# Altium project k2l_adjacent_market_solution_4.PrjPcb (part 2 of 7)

## Sheet k2l_soc_03_1.SchDoc
size 431 x 279 mm; Date: Not shown in title block; ApprovedBy: Not shown in title block; CheckedBy: Not shown in title block; Author: Not shown in title block; CompanyName: Not shown in title block; Engineer: Not shown in title block; Organization: Not shown in title block; Address1: Not shown in title block; Address2: Not shown in title block; Address3: Not shown in title block; Address4: Not shown in title block; DocumentNumber: 8; Revision: Use project parameter SCH_Rev; SheetNumber: 8; SheetTotal: 38; PageSetup: Record=PageOptions¦CenterHorizontal=True¦CenterVertical=True¦PrintScale=1.00¦XCorrection=1.00¦YCorrection=1.00¦PrintKind=0¦BorderSize=5000000¦LeftOffset=0¦BottomOffset=0¦Orientation=2¦PaperLength=1000¦PaperWidth=1000¦Scale=100¦PaperSource=15¦PrintQuality=600¦MediaType=1¦DitherType=10¦PaperKind=Letter¦PrintScaleMode=1
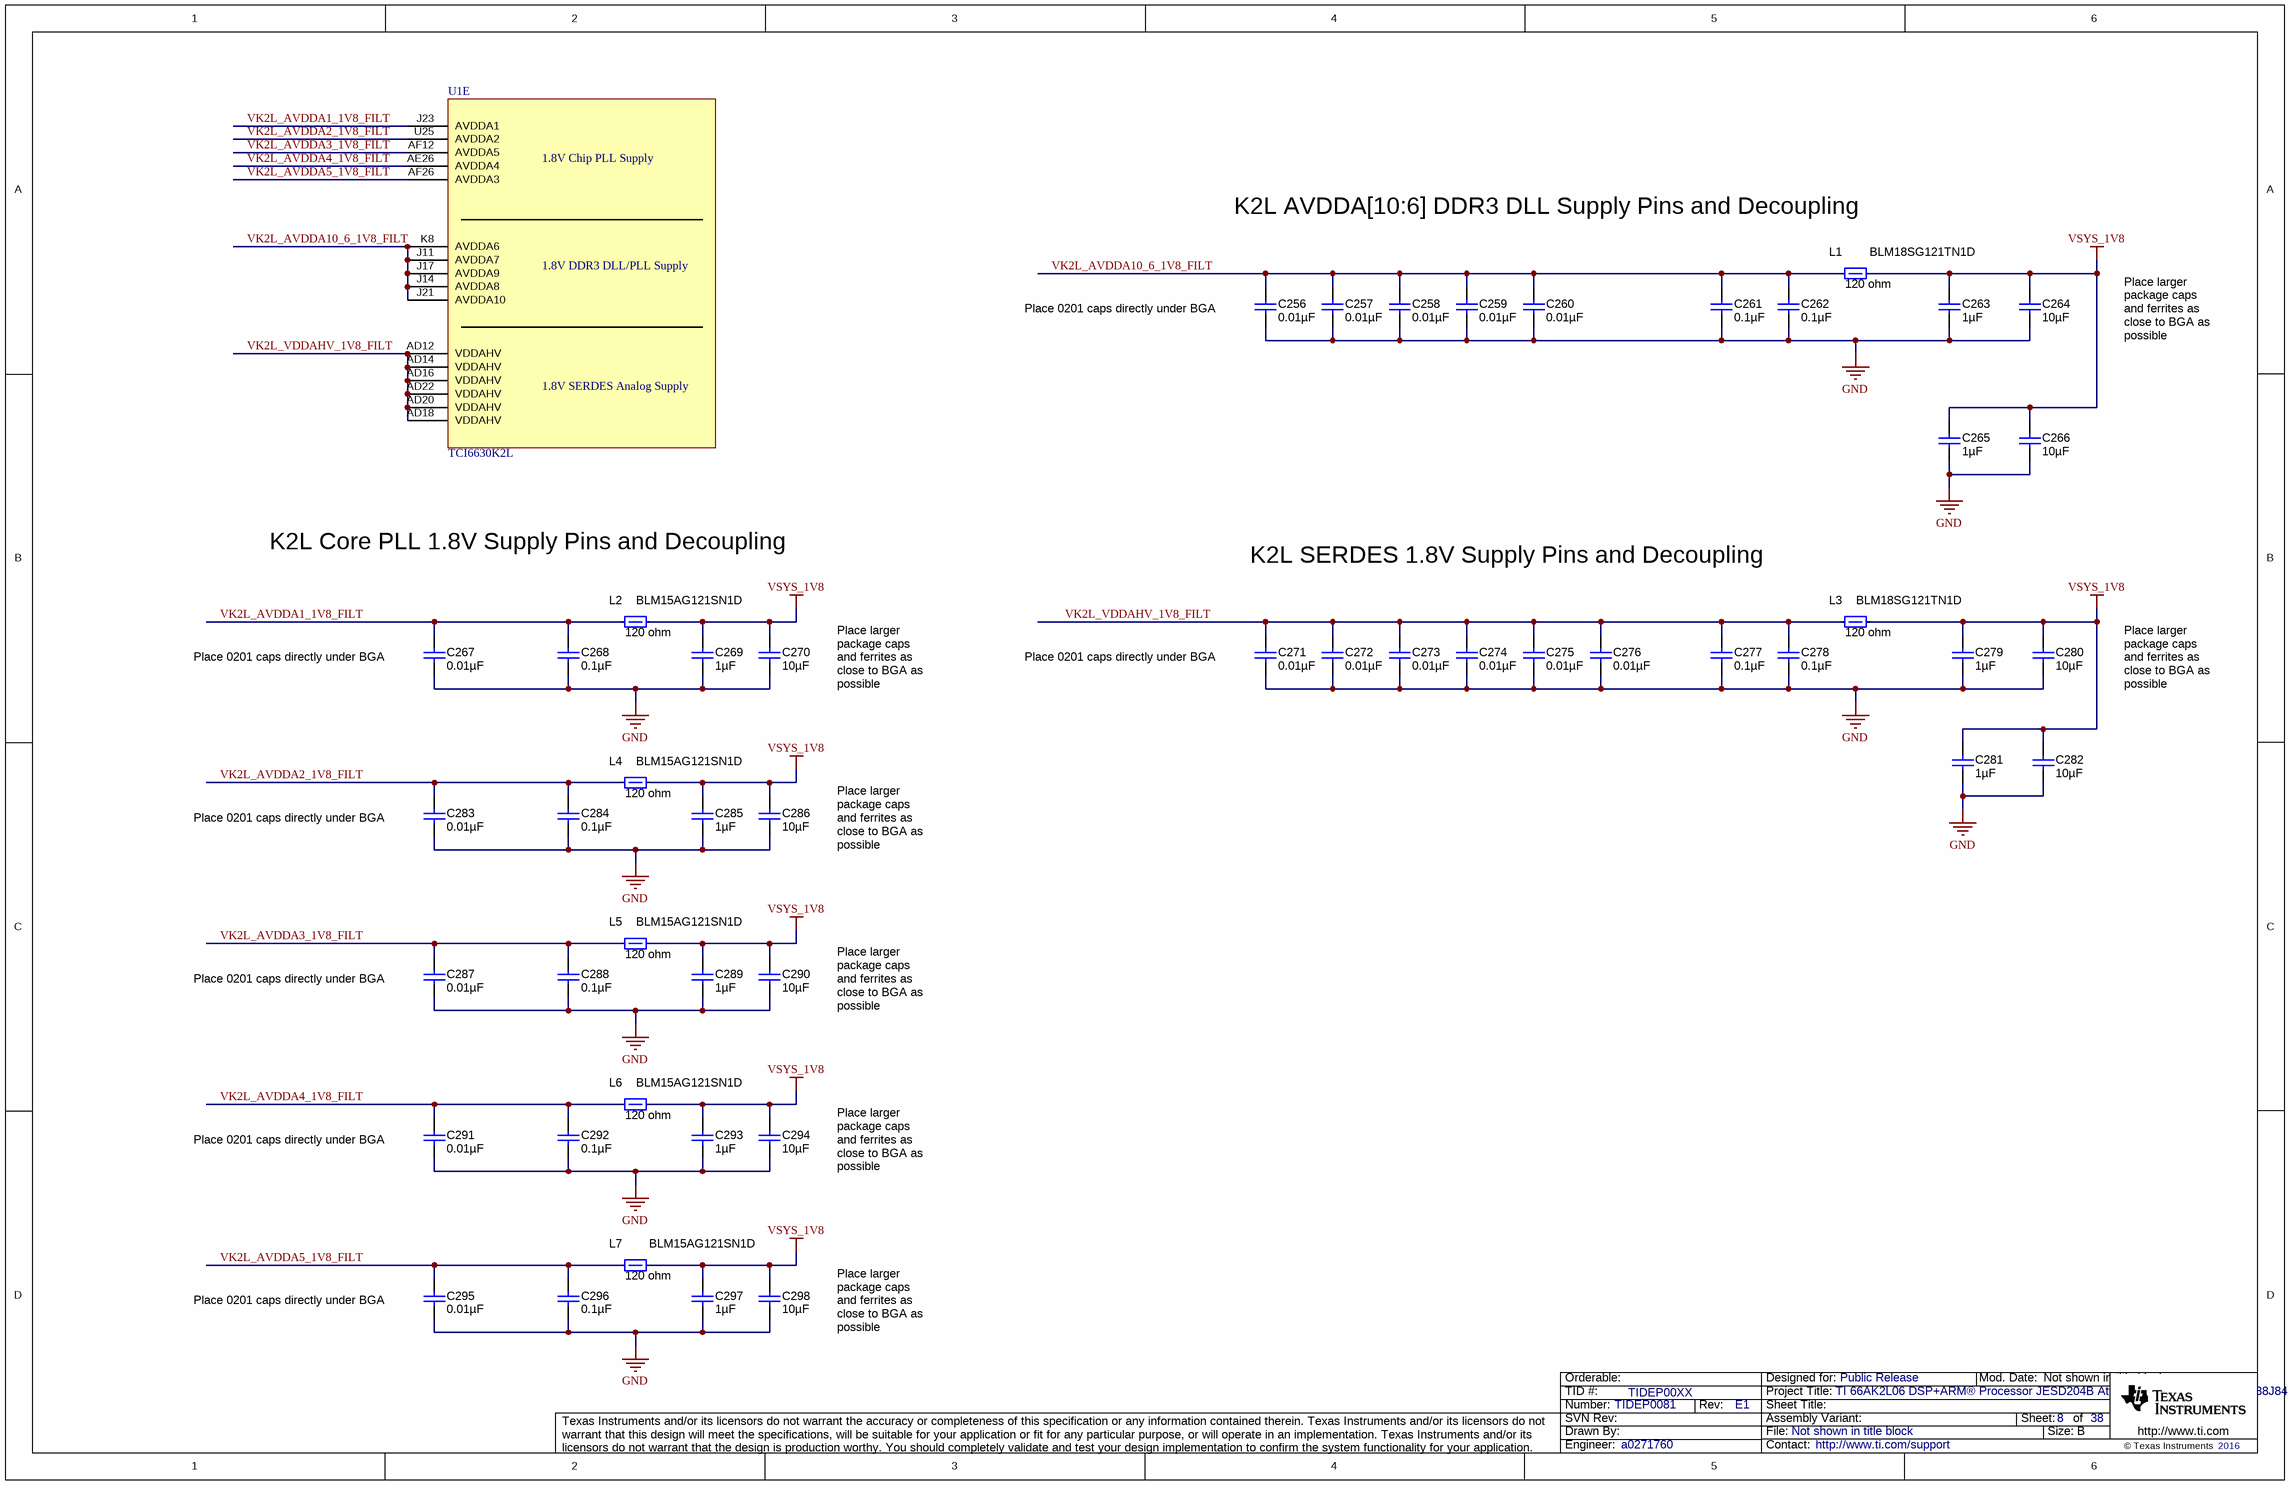
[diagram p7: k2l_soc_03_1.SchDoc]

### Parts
C256  ValueDisplayed: 0.01µF  [0201]  (hidden comment: GRM033R60J103KA01D)
C257  ValueDisplayed: 0.01µF  [0201]  (hidden comment: GRM033R60J103KA01D)
C258  ValueDisplayed: 0.01µF  [0201]  (hidden comment: GRM033R60J103KA01D)
C259  ValueDisplayed: 0.01µF  [0201]  (hidden comment: GRM033R60J103KA01D)
C260  ValueDisplayed: 0.01µF  [0201]  (hidden comment: GRM033R60J103KA01D)
C261  ValueDisplayed: 0.1µF  [0603]  (hidden comment: GRM188R70J104KA01D)
C262  ValueDisplayed: 0.1µF  [0603]  (hidden comment: GRM188R70J104KA01D)
C263  ValueDisplayed: 1µF  [0603]  (hidden comment: GRM188R70J105KA01D)
C264  ValueDisplayed: 10µF  [0805_HV]  (hidden comment: GRM21BF50J106ZE01L)
C265  ValueDisplayed: 1µF  [0603]  (hidden comment: GRM188R70J105KA01D)
C266  ValueDisplayed: 10µF  [0805_HV]  (hidden comment: GRM21BF50J106ZE01L)
C267  ValueDisplayed: 0.01µF  [0201]  (hidden comment: GRM033R60J103KA01D)
C268  ValueDisplayed: 0.1µF  [0603]  (hidden comment: GRM188R70J104KA01D)
C269  ValueDisplayed: 1µF  [0603]  (hidden comment: GRM188R70J105KA01D)
C270  ValueDisplayed: 10µF  [0805_HV]  (hidden comment: GRM21BF50J106ZE01L)
C271  ValueDisplayed: 0.01µF  [0201]  (hidden comment: GRM033R60J103KA01D)
C272  ValueDisplayed: 0.01µF  [0201]  (hidden comment: GRM033R60J103KA01D)
C273  ValueDisplayed: 0.01µF  [0201]  (hidden comment: GRM033R60J103KA01D)
C274  ValueDisplayed: 0.01µF  [0201]  (hidden comment: GRM033R60J103KA01D)
C275  ValueDisplayed: 0.01µF  [0201]  (hidden comment: GRM033R60J103KA01D)
C276  ValueDisplayed: 0.01µF  [0201]  (hidden comment: GRM033R60J103KA01D)
C277  ValueDisplayed: 0.1µF  [0603]  (hidden comment: GRM188R70J104KA01D)
C278  ValueDisplayed: 0.1µF  [0603]  (hidden comment: GRM188R70J104KA01D)
C279  ValueDisplayed: 1µF  [0603]  (hidden comment: GRM188R70J105KA01D)
C280  ValueDisplayed: 10µF  [0805_HV]  (hidden comment: GRM21BF50J106ZE01L)
C281  ValueDisplayed: 1µF  [0603]  (hidden comment: GRM188R70J105KA01D)
C282  ValueDisplayed: 10µF  [0805_HV]  (hidden comment: GRM21BF50J106ZE01L)
C283  ValueDisplayed: 0.01µF  [0201]  (hidden comment: GRM033R60J103KA01D)
C284  ValueDisplayed: 0.1µF  [0603]  (hidden comment: GRM188R70J104KA01D)
C285  ValueDisplayed: 1µF  [0603]  (hidden comment: GRM188R70J105KA01D)
C286  ValueDisplayed: 10µF  [0805_HV]  (hidden comment: GRM21BF50J106ZE01L)
C287  ValueDisplayed: 0.01µF  [0201]  (hidden comment: GRM033R60J103KA01D)
C288  ValueDisplayed: 0.1µF  [0603]  (hidden comment: GRM188R70J104KA01D)
C289  ValueDisplayed: 1µF  [0603]  (hidden comment: GRM188R70J105KA01D)
C290  ValueDisplayed: 10µF  [0805_HV]  (hidden comment: GRM21BF50J106ZE01L)
C291  ValueDisplayed: 0.01µF  [0201]  (hidden comment: GRM033R60J103KA01D)
C292  ValueDisplayed: 0.1µF  [0603]  (hidden comment: GRM188R70J104KA01D)
C293  ValueDisplayed: 1µF  [0603]  (hidden comment: GRM188R70J105KA01D)
C294  ValueDisplayed: 10µF  [0805_HV]  (hidden comment: GRM21BF50J106ZE01L)
C295  ValueDisplayed: 0.01µF  [0201]  (hidden comment: GRM033R60J103KA01D)
C296  ValueDisplayed: 0.1µF  [0603]  (hidden comment: GRM188R70J104KA01D)
C297  ValueDisplayed: 1µF  [0603]  (hidden comment: GRM188R70J105KA01D)
C298  ValueDisplayed: 10µF  [0805_HV]  (hidden comment: GRM21BF50J106ZE01L)
L1  BLM18SG121TN1D  value 120 ohm  [0603]
L2  value 120 ohm  [0402]  (hidden comment: BLM15AG121SN1D)
L3  BLM18SG121TN1D  value 120 ohm  [0603]
L4  BLM15AG121SN1D  value 120 ohm  [0402]
L5  BLM15AG121SN1D  value 120 ohm  [0402]
L6  BLM15AG121SN1D  value 120 ohm  [0402]
L7  BLM15AG121SN1D  value 120 ohm  [0402]
U1  TCI6630K2L  [BGA900C80P30X30_2500X2500X355]  (part E of 24)

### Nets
GND: C256.2 C257.2 C258.2 C259.2 C260.2 C261.2 C262.2 C263.2 C264.2 C265.2 C266.2 C267.2 C268.2 C269.2 C270.2 C271.2 C272.2 C273.2 C274.2 C275.2 C276.2 C277.2 C278.2 C279.2 C280.2 C281.2 C282.2 C283.2 C284.2 C285.2 C286.2 C287.2 C288.2 C289.2 C290.2 C291.2 C292.2 C293.2 C294.2 C295.2 C296.2 C297.2 C298.2  [project net DAC_OUT0N_T1]
VSYS_1V8: C263.1 C264.1 C265.1 C266.1 C269.1 C270.1 C279.1 C280.1 C281.1 C282.1 C285.1 C286.1 C289.1 C290.1 C293.1 C294.1 C297.1 C298.1 L1.2 L2.2 L3.2 L4.2 L5.2 L6.2 L7.2
VK2L_AVDDA1_1V8_FILT: C267.1 C268.1 L2.1 U1.J23(AVDDA1)
VK2L_AVDDA2_1V8_FILT: C283.1 C284.1 L4.1 U1.U25(AVDDA2)
VK2L_AVDDA3_1V8_FILT: C287.1 C288.1 L5.1 U1.AF12(AVDDA5)
VK2L_AVDDA4_1V8_FILT: C291.1 C292.1 L6.1 U1.AE26(AVDDA4)
VK2L_AVDDA5_1V8_FILT: C295.1 C296.1 L7.1 U1.AF26(AVDDA3)
VK2L_AVDDA10_6_1V8_FILT: C256.1 C257.1 C258.1 C259.1 C260.1 C261.1 C262.1 L1.1 U1.J11(AVDDA7) U1.J14(AVDDA8) U1.J17(AVDDA9) U1.J21(AVDDA10) U1.K8(AVDDA6)
VK2L_VDDAHV_1V8_FILT: C271.1 C272.1 C273.1 C274.1 C275.1 C276.1 C277.1 C278.1 L3.1 U1.AD12(VDDAHV) U1.AD14(VDDAHV) U1.AD16(VDDAHV) U1.AD18(VDDAHV) U1.AD20(VDDAHV) U1.AD22(VDDAHV)

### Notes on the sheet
- K2L AVDDA[10:6] DDR3 DLL Supply Pins and Decoupling
- (near C256) Place 0201 caps directly under BGA
- Place larger package caps and ferrites as close to BGA as possible
- K2L Core PLL 1.8V Supply Pins and Decoupling
- K2L SERDES 1.8V Supply Pins and Decoupling
- (near C267) Place 0201 caps directly under BGA
- (near C271) Place 0201 caps directly under BGA
- (near C283) Place 0201 caps directly under BGA
- (near C287) Place 0201 caps directly under BGA
- (near C291) Place 0201 caps directly under BGA
- (near C295) Place 0201 caps directly under BGA

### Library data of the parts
C256-C260 C267 C271-C276 C283 C287 C291 C295 = GRM033R60J103KA01D: CAP, CERM, 0.01 µF, 6.3 V, +/- 10%, X5R, 0201; Manufacturer: MuRata; Polarized: N; CompType: Capacitor; Value: 0.01uF; U/M: EA; Cap_F: 0.00000001; Tolerance_%: 10; Value1: Unknown; VDC_V: 6.3; Value2: 6.3V; TaMin_C: -55; TaMax_C: 85; SizeArea_mm2: 0.18; SizeAreaWB_mm2: 2.08; SizeX_mm: 0.6; SizeY_mm: 0.3; SizeZ_mm: 0.26; AEC Category: Q200
C261 C262 C268 C277 C278 C284 C288 C292 C296 = GRM188R70J104KA01D: CAP, CERM, 0.1 µF, 6.3 V, +/- 10%, X7R, 0603; Manufacturer: MuRata; Polarized: N; CompType: Capacitor; Value: 0.1uF; U/M: EA; Cap_F: 0.0000001; Tolerance_%: 10; Value1: Unknown; VDC_V: 6.3; Value2: 6.3V; TaMin_C: -55; TaMax_C: 125; SizeArea_mm2: 1.28; SizeAreaWB_mm2: 4.68; SizeX_mm: 1.6; SizeY_mm: 0.8; SizeZ_mm: 1; AEC Category: Q200
C263 C265 C269 C279 C281 C285 C289 C293 C297 = GRM188R70J105KA01D: CAP, CERM, 1 µF, 6.3 V, +/- 10%, X7R, 0603; Manufacturer: MuRata; Polarized: N; CompType: Capacitor; Value: 1uF; U/M: EA; Cap_F: 0.000001; Tolerance_%: 10; Value1: Unknown; VDC_V: 6.3; Value2: 6.3V; TaMin_C: -55; TaMax_C: 125; SizeArea_mm2: 1.28; SizeAreaWB_mm2: 4.68; SizeX_mm: 1.6; SizeY_mm: 0.8; SizeZ_mm: 1; AEC Category: Q200
C264 C266 C270 C280 C282 C286 C290 C294 C298 = GRM21BF50J106ZE01L: CAP, CERM, 10 µF, 6.3 V, +80/-20%, Y5V, 0805; Manufacturer: MuRata; Polarized: N; CompType: Capacitor; Value: 10uF; U/M: EA; Cap_F: 0.00001; Tolerance_%: 80; ESR_ohm: 0.1; Value1: 0.1 ohm; VDC_V: 6.3; Value2: 6.3V; TaMin_C: -30; TaMax_C: 85; Cap_Case: 0805; SizeArea_mm2: 2.5; SizeAreaWB_mm2: 6.75; SizeX_mm: 2; SizeY_mm: 1.25; SizeZ_mm: 1.45; AEC Category: Q200
L1 L3 = BLM18SG121TN1D: Ferrite Bead, 120 ohm @ 100 MHz, 3 A, 0603; Manufacturer: MuRata; Imax_A: 3; DCR_ohm: 0.025; Value1: 0.025 ohm; Value2: 3A; ZTyp@100MHz_Ohm: 120
L2 L4-L7 = BLM15AG121SN1D: Ferrite Bead, 120 ohm @ 100 MHz, 0.55 A, 0402; Manufacturer: MuRata; Imax_A: 0.55; DCR_ohm: 0.19; Value1: 0.19 ohm; Value2: 0.55A; ZTyp@100MHz_Ohm: 120
U1 = lamarr_soc_TCI6630K2L: Smallcell Baseband Processor with 4 C66x DSP Cores / 2 ARM A15 Cores / JESD / CPRI...etc

## Sheet k2l_soc_04.SchDoc
size 431 x 279 mm; Date: Not shown in title block; ApprovedBy: Not shown in title block; CheckedBy: Not shown in title block; Author: Not shown in title block; CompanyName: Not shown in title block; Engineer: Not shown in title block; Organization: Not shown in title block; Address1: Not shown in title block; Address2: Not shown in title block; Address3: Not shown in title block; Address4: Not shown in title block; DocumentNumber: 9; Revision: Use project parameter SCH_Rev; SheetNumber: 9; SheetTotal: 38; PageSetup: Record=PageOptions¦CenterHorizontal=True¦CenterVertical=True¦PrintScale=1.00¦XCorrection=1.00¦YCorrection=1.00¦PrintKind=0¦BorderSize=5000000¦LeftOffset=0¦BottomOffset=0¦Orientation=2¦PaperLength=1000¦PaperWidth=1000¦Scale=100¦PaperSource=15¦PrintQuality=600¦MediaType=1¦DitherType=10¦PaperKind=Letter¦PrintScaleMode=1
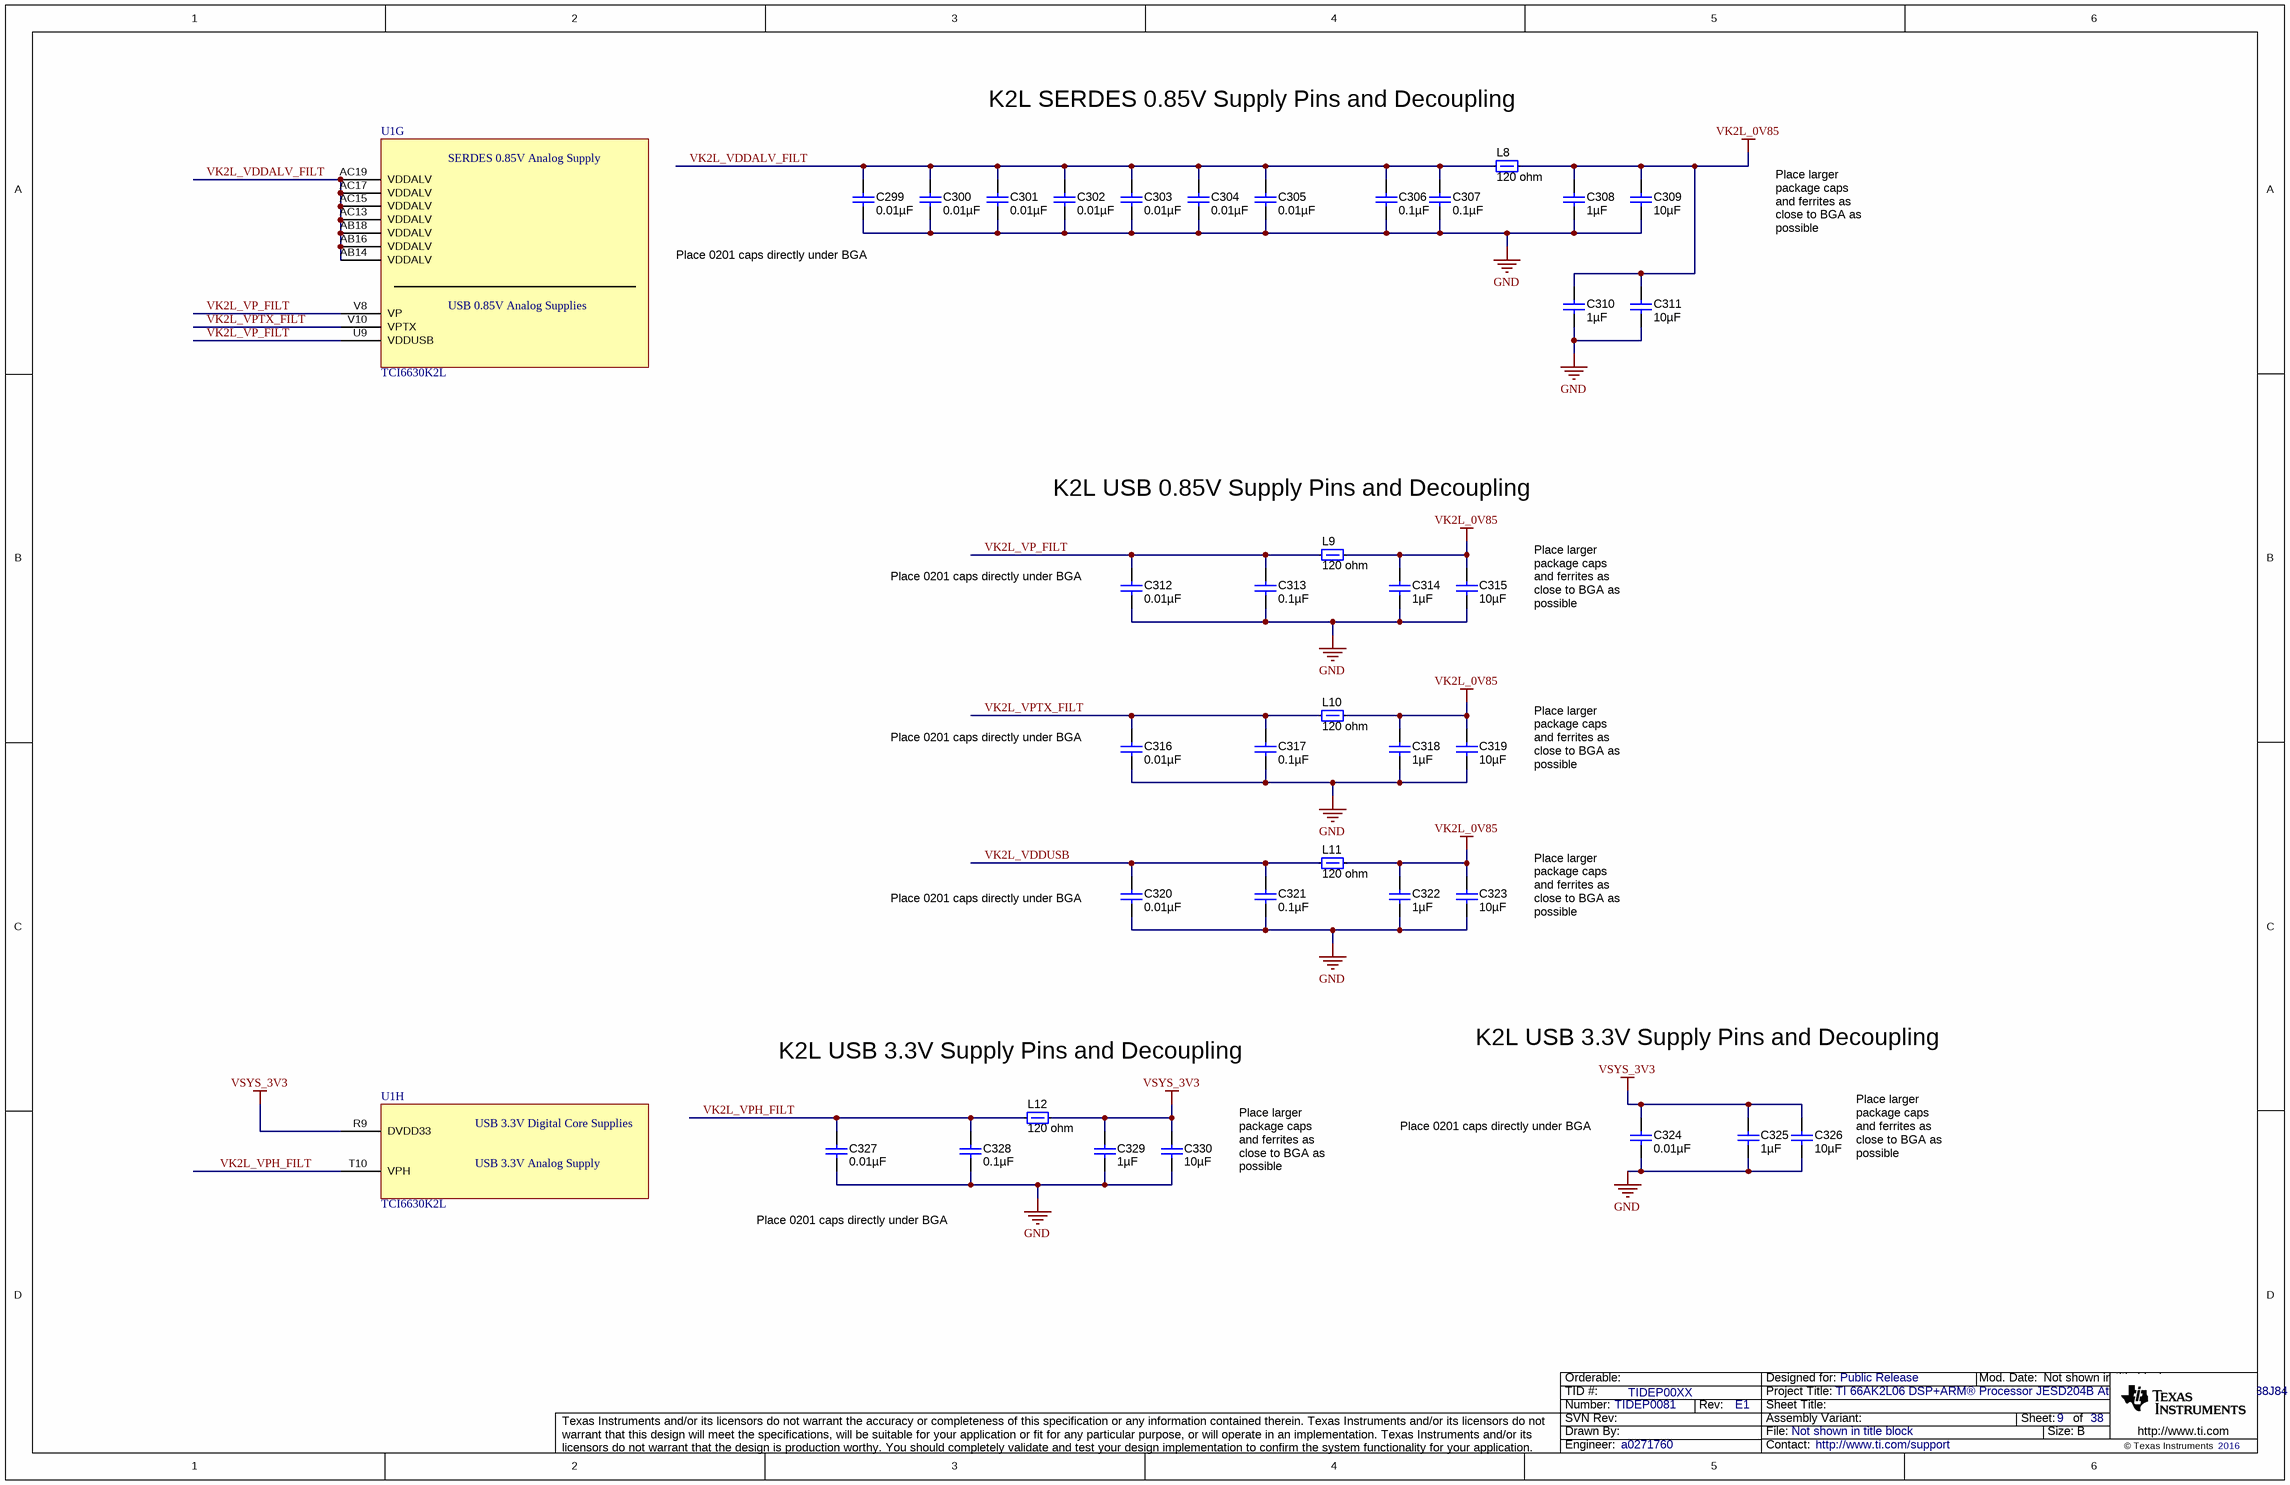
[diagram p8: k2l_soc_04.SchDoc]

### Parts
C299  ValueDisplayed: 0.01µF  [0201]  (hidden comment: GRM033R60J103KA01D)
C300  ValueDisplayed: 0.01µF  [0201]  (hidden comment: GRM033R60J103KA01D)
C301  ValueDisplayed: 0.01µF  [0201]  (hidden comment: GRM033R60J103KA01D)
C302  ValueDisplayed: 0.01µF  [0201]  (hidden comment: GRM033R60J103KA01D)
C303  ValueDisplayed: 0.01µF  [0201]  (hidden comment: GRM033R60J103KA01D)
C304  ValueDisplayed: 0.01µF  [0201]  (hidden comment: GRM033R60J103KA01D)
C305  ValueDisplayed: 0.01µF  [0201]  (hidden comment: GRM033R60J103KA01D)
C306  ValueDisplayed: 0.1µF  [0603]  (hidden comment: GRM188R70J104KA01D)
C307  ValueDisplayed: 0.1µF  [0603]  (hidden comment: GRM188R70J104KA01D)
C308  ValueDisplayed: 1µF  [0603]  (hidden comment: GRM188R70J105KA01D)
C309  ValueDisplayed: 10µF  [0805_HV]  (hidden comment: GRM21BF50J106ZE01L)
C310  ValueDisplayed: 1µF  [0603]  (hidden comment: GRM188R70J105KA01D)
C311  ValueDisplayed: 10µF  [0805_HV]  (hidden comment: GRM21BF50J106ZE01L)
C312  ValueDisplayed: 0.01µF  [0201]  (hidden comment: GRM033R60J103KA01D)
C313  ValueDisplayed: 0.1µF  [0603]  (hidden comment: GRM188R70J104KA01D)
C314  ValueDisplayed: 1µF  [0603]  (hidden comment: GRM188R70J105KA01D)
C315  ValueDisplayed: 10µF  [0805_HV]  (hidden comment: GRM21BF50J106ZE01L)
C316  ValueDisplayed: 0.01µF  [0201]  (hidden comment: GRM033R60J103KA01D)
C317  ValueDisplayed: 0.1µF  [0603]  (hidden comment: GRM188R70J104KA01D)
C318  ValueDisplayed: 1µF  [0603]  (hidden comment: GRM188R70J105KA01D)
C319  ValueDisplayed: 10µF  [0805_HV]  (hidden comment: GRM21BF50J106ZE01L)
C320  ValueDisplayed: 0.01µF  [0201]  (hidden comment: GRM033R60J103KA01D)
C321  ValueDisplayed: 0.1µF  [0603]  (hidden comment: GRM188R70J104KA01D)
C322  ValueDisplayed: 1µF  [0603]  (hidden comment: GRM188R70J105KA01D)
C323  ValueDisplayed: 10µF  [0805_HV]  (hidden comment: GRM21BF50J106ZE01L)
C324  ValueDisplayed: 0.01µF  [0201]  (hidden comment: GRM033R60J103KA01D)
C325  ValueDisplayed: 1µF  [0603]  (hidden comment: GRM188R70J105KA01D)
C326  ValueDisplayed: 10µF  [0805_HV]  (hidden comment: GRM21BF50J106ZE01L)
C327  ValueDisplayed: 0.01µF  [0201]  (hidden comment: GRM033R60J103KA01D)
C328  ValueDisplayed: 0.1µF  [0603]  (hidden comment: GRM188R70J104KA01D)
C329  ValueDisplayed: 1µF  [0603]  (hidden comment: GRM188R70J105KA01D)
C330  ValueDisplayed: 10µF  [0805_HV]  (hidden comment: GRM21BF50J106ZE01L)
L8  value 120 ohm  [0603]  (hidden comment: BLM18SG121TN1D)
L9  value 120 ohm  [0402]  (hidden comment: BLM15AG121SN1D)
L10  value 120 ohm  [0402]  (hidden comment: BLM15AG121SN1D)
L11  value 120 ohm  [0402]  (hidden comment: BLM15AG121SN1D)
L12  value 120 ohm  [0402]  (hidden comment: BLM15AG121SN1D)
U1  TCI6630K2L  [BGA900C80P30X30_2500X2500X355]  (parts G,H of 24)

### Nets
GND: C299.2 C300.2 C301.2 C302.2 C303.2 C304.2 C305.2 C306.2 C307.2 C308.2 C309.2 C310.2 C311.2 C312.2 C313.2 C314.2 C315.2 C316.2 C317.2 C318.2 C319.2 C320.2 C321.2 C322.2 C323.2 C324.2 C325.2 C326.2 C327.2 C328.2 C329.2 C330.2  [project net DAC_OUT0N_T1]
VK2L_0V85: C308.1 C309.1 C310.1 C311.1 C314.1 C315.1 C318.1 C319.1 C322.1 C323.1 L8.2 L9.2 L10.2 L11.2
VSYS_3V3: C324.1 C325.1 C326.1 C329.1 C330.1 L12.2 U1.R9(DVDD33)
VK2L_VDDALV_FILT: C299.1 C300.1 C301.1 C302.1 C303.1 C304.1 C305.1 C306.1 C307.1 L8.1 U1.AB14(VDDALV) U1.AB16(VDDALV) U1.AB18(VDDALV) U1.AC13(VDDALV) U1.AC15(VDDALV) U1.AC17(VDDALV) U1.AC19(VDDALV)
VK2L_VDDUSB: C320.1 C321.1 L11.1
VK2L_VP_FILT: C312.1 C313.1 L9.1 U1.U9(VDDUSB) U1.V8(VP)
VK2L_VPH_FILT: C327.1 C328.1 L12.1 U1.T10(VPH)
VK2L_VPTX_FILT: C316.1 C317.1 L10.1 U1.V10(VPTX)

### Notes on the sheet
- K2L SERDES 0.85V Supply Pins and Decoupling
- Place 0201 caps directly under BGA
- Place larger package caps and ferrites as close to BGA as possible
- K2L USB 0.85V Supply Pins and Decoupling
- (near C312) Place 0201 caps directly under BGA
- (near C316) Place 0201 caps directly under BGA
- (near C320) Place 0201 caps directly under BGA
- K2L USB 3.3V Supply Pins and Decoupling
- (near C324) Place 0201 caps directly under BGA

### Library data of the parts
C299-C305 C312 C316 C320 C324 C327 = GRM033R60J103KA01D: as C256-C260 on sheet k2l_soc_03_1
C306 C307 C313 C317 C321 C328 = GRM188R70J104KA01D: as C261 on sheet k2l_soc_03_1
C308 C310 C314 C318 C322 C325 C329 = GRM188R70J105KA01D: as C263 on sheet k2l_soc_03_1
C309 C311 C315 C319 C323 C326 C330 = GRM21BF50J106ZE01L: as C264 on sheet k2l_soc_03_1
L8 = BLM18SG121TN1D: as L1 on sheet k2l_soc_03_1
L9-L12 = BLM15AG121SN1D: as L2 on sheet k2l_soc_03_1
U1 = lamarr_soc_TCI6630K2L: as U1 on sheet k2l_soc_03_1

## Sheet k2l_soc_05.SchDoc
size 431 x 279 mm; Date: Not shown in title block; ApprovedBy: Not shown in title block; CheckedBy: Not shown in title block; Author: Not shown in title block; CompanyName: Not shown in title block; Engineer: Not shown in title block; Organization: Not shown in title block; Address1: Not shown in title block; Address2: Not shown in title block; Address3: Not shown in title block; Address4: Not shown in title block; DocumentNumber: 10; Revision: Use project parameter SCH_Rev; SheetNumber: 10; SheetTotal: 38; PageSetup: Record=PageOptions¦CenterHorizontal=True¦CenterVertical=True¦PrintScale=1.00¦XCorrection=1.00¦YCorrection=1.00¦PrintKind=0¦BorderSize=5000000¦LeftOffset=0¦BottomOffset=0¦Orientation=2¦PaperLength=1000¦PaperWidth=1000¦Scale=100¦PaperSource=15¦PrintQuality=600¦MediaType=1¦DitherType=10¦PaperKind=Letter¦PrintScaleMode=1
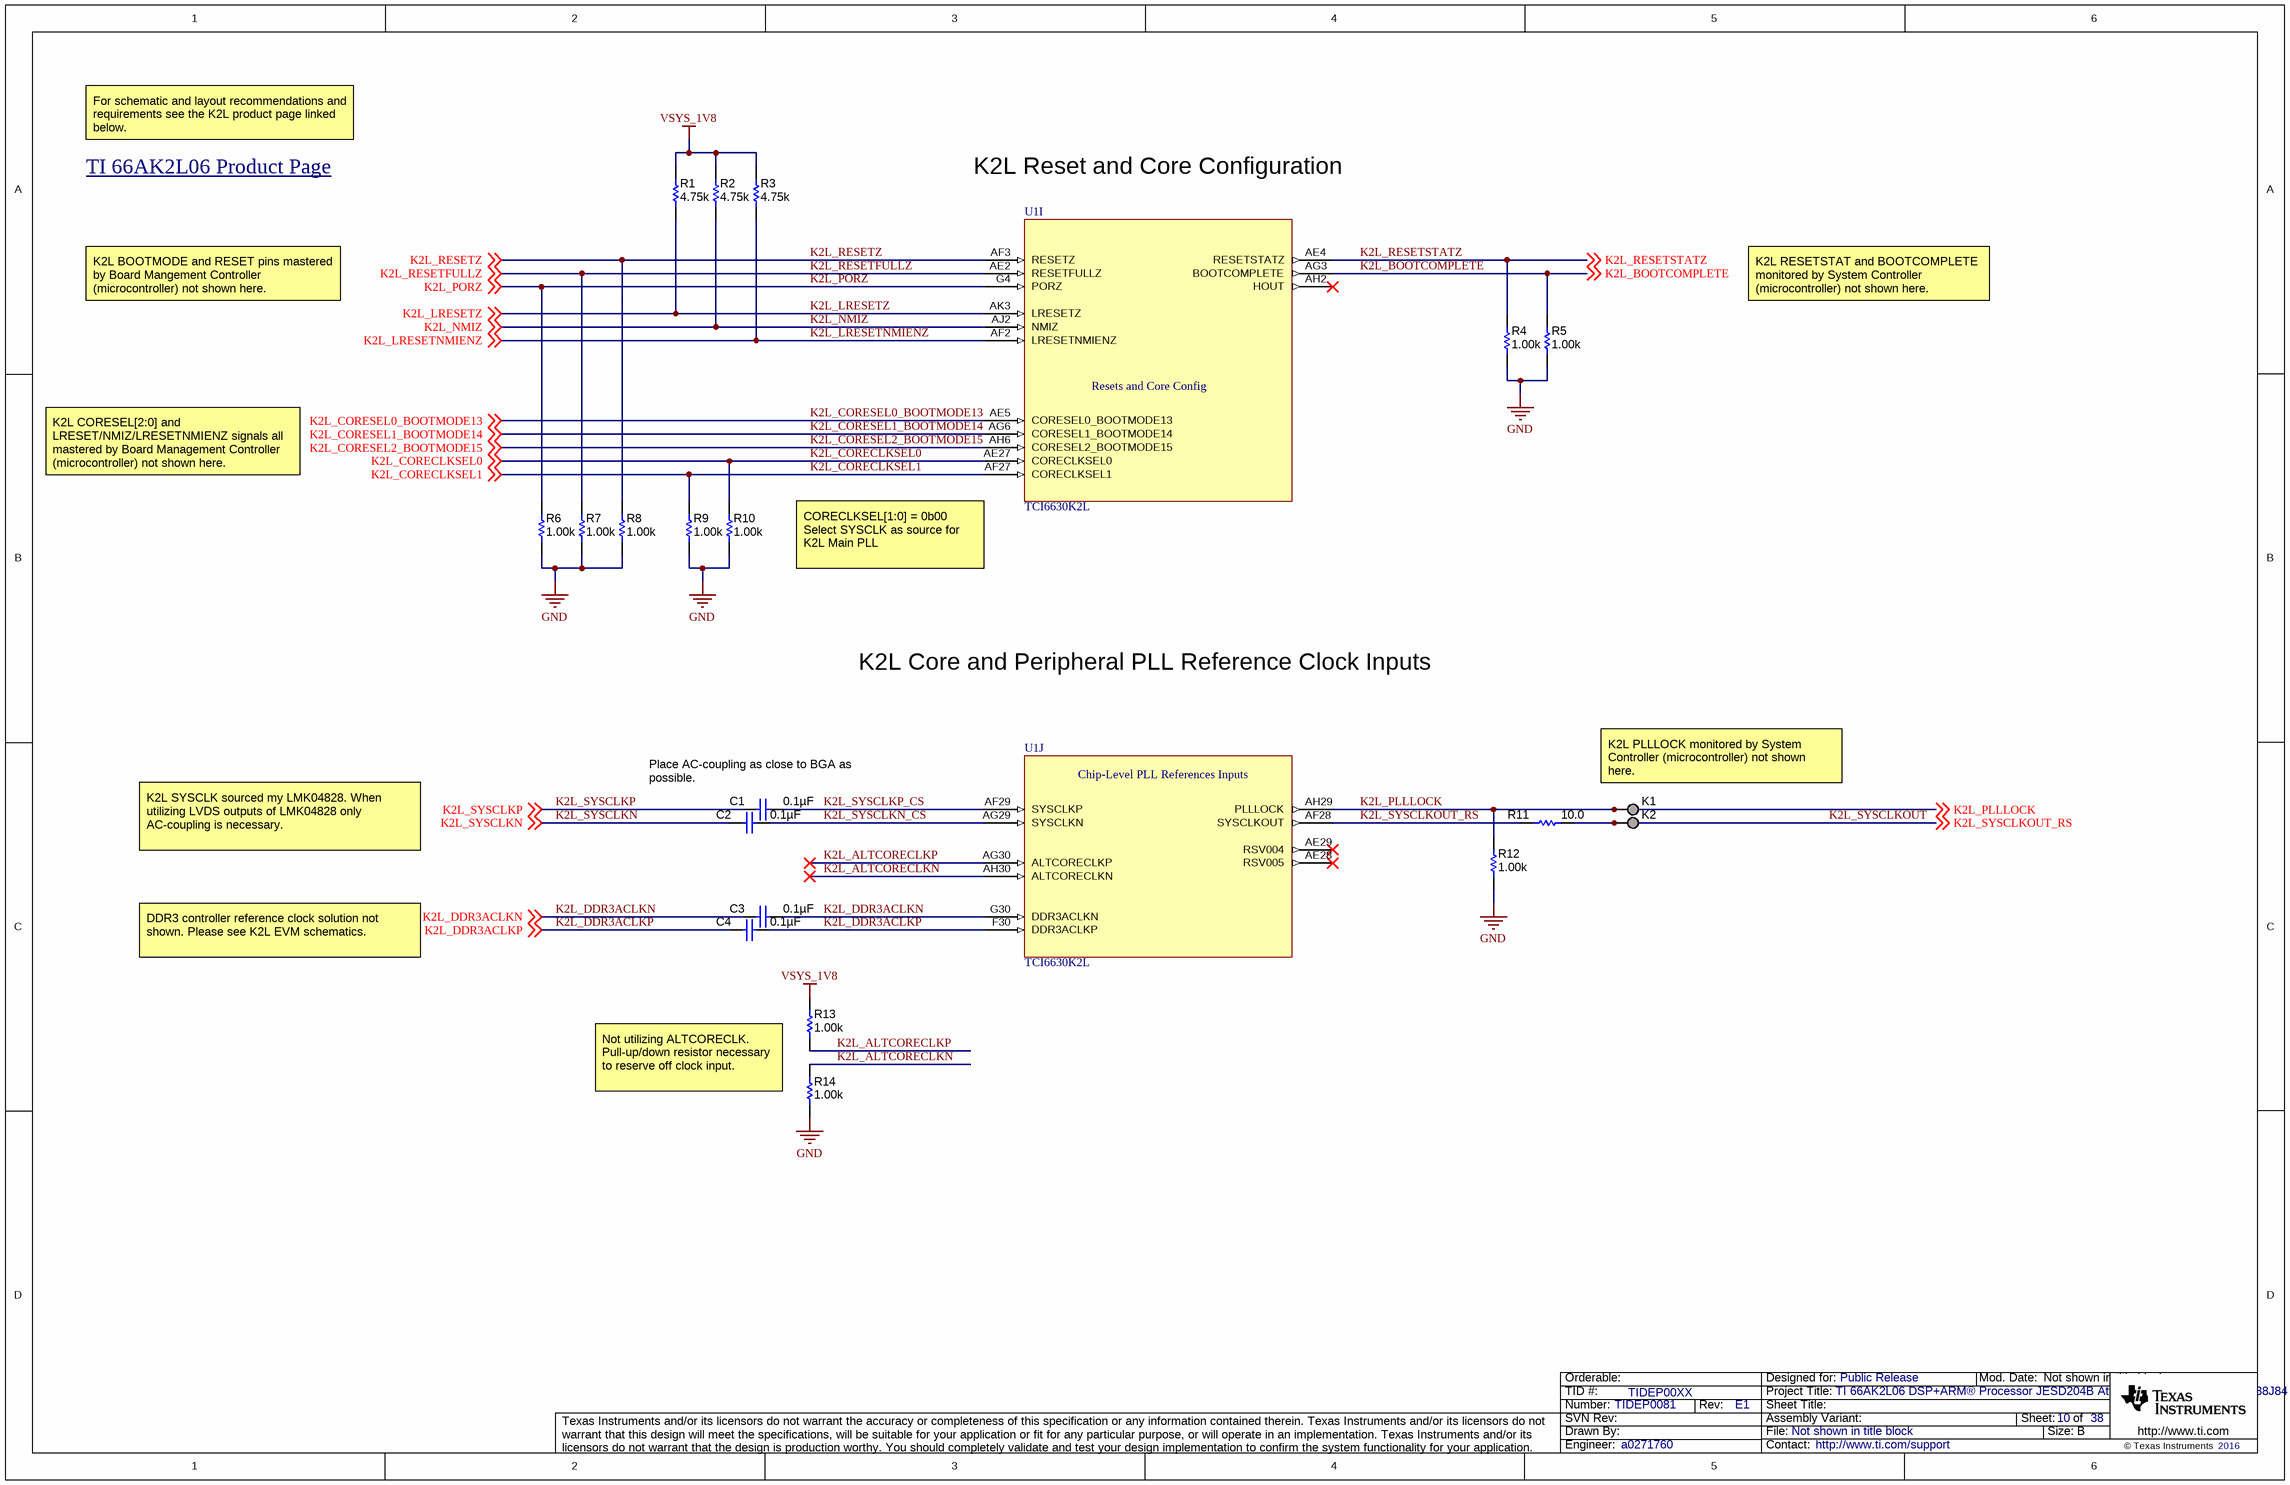
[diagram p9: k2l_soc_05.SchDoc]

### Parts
C1  ValueDisplayed: 0.1µF  [0201]  (hidden comment: C0603X5R0J104K030BC)
C2  ValueDisplayed: 0.1µF  [0201]  (hidden comment: C0603X5R0J104K030BC)
C3  ValueDisplayed: 0.1µF  [0201]  (hidden comment: C0603X5R0J104K030BC)
C4  ValueDisplayed: 0.1µF  [0201]  (hidden comment: C0603X5R0J104K030BC)
K1  TESTPOINT  [TESTPOINT]  (value not drawn)  (no BOM)
K2  TESTPOINT  [TESTPOINT]  (value not drawn)  (no BOM)
R1  ValueDisplayed: 4.75k  [0402]  (hidden comment: CRCW04024K75FKED)
R2  ValueDisplayed: 4.75k  [0402]  (hidden comment: CRCW04024K75FKED)
R3  ValueDisplayed: 4.75k  [0402]  (hidden comment: CRCW04024K75FKED)
R4  ValueDisplayed: 1.00k  [0402]  (hidden comment: CRCW04021K00FKED)
R5  ValueDisplayed: 1.00k  [0402]  (hidden comment: CRCW04021K00FKED)
R6  ValueDisplayed: 1.00k  [0402]  (hidden comment: CRCW04021K00FKED)
R7  ValueDisplayed: 1.00k  [0402]  (hidden comment: CRCW04021K00FKED)
R8  ValueDisplayed: 1.00k  [0402]  (hidden comment: CRCW04021K00FKED)
R9  ValueDisplayed: 1.00k  [0402]  (hidden comment: CRCW04021K00FKED)
R10  ValueDisplayed: 1.00k  [0402]  (hidden comment: CRCW04021K00FKED)
R11  ValueDisplayed: 10.0  [0402]  (hidden comment: CRCW040210R0FKED)
R12  ValueDisplayed: 1.00k  [0402]  (hidden comment: CRCW04021K00FKED)
R13  ValueDisplayed: 1.00k  [0402]  (hidden comment: CRCW04021K00FKED)
R14  ValueDisplayed: 1.00k  [0402]  (hidden comment: CRCW04021K00FKED)
U1  TCI6630K2L  [BGA900C80P30X30_2500X2500X355]  (parts I,J of 24)

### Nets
GND: R4.1 R5.1 R6.1 R7.1 R8.1 R9.1 R10.1 R12.1 R14.1  [project net DAC_OUT0N_T1]
VSYS_1V8: R1.2 R2.2 R3.2 R13.2
K2L_ALTCORECLKN: R14.2 U1.AH30(ALTCORECLKN)
K2L_ALTCORECLKP: R13.1 U1.AG30(ALTCORECLKP)
K2L_BOOTCOMPLETE: R5.2 U1.AG3(BOOTCOMPLETE) ; off-sheet K2L_BOOTCOMPLETE
K2L_CORECLKSEL0: R10.2 U1.AE27(CORECLKSEL0) ; off-sheet K2L_CORECLKSEL0
K2L_CORECLKSEL1: R9.2 U1.AF27(CORECLKSEL1) ; off-sheet K2L_CORECLKSEL1
K2L_CORESEL0_BOOTMODE13: U1.AE5(CORESEL0_BOOTMODE13) ; off-sheet K2L_CORESEL0_BOOTMODE13
K2L_CORESEL1_BOOTMODE14: U1.AG6(CORESEL1_BOOTMODE14) ; off-sheet K2L_CORESEL1_BOOTMODE14
K2L_CORESEL2_BOOTMODE15: U1.AH6(CORESEL2_BOOTMODE15) ; off-sheet K2L_CORESEL2_BOOTMODE15
K2L_DDR3ACLKN: C3.1 C3.2 U1.G30(DDR3ACLKN) ; off-sheet K2L_DDR3ACLKN
K2L_DDR3ACLKP: C4.1 C4.2 U1.F30(DDR3ACLKP) ; off-sheet K2L_DDR3ACLKP
K2L_LRESETNMIENZ: R3.1 U1.AF2(LRESETNMIENZ) ; off-sheet K2L_LRESETNMIENZ
K2L_LRESETZ: R1.1 U1.AK3(LRESETZ) ; off-sheet K2L_LRESETZ
K2L_NMIZ: R2.1 U1.AJ2(NMIZ) ; off-sheet K2L_NMIZ
K2L_PLLLOCK: K1.1 R12.2 U1.AH29(PLLLOCK) ; off-sheet K2L_PLLLOCK
K2L_PORZ: R6.2 U1.G4(PORZ) ; off-sheet K2L_PORZ
K2L_RESETFULLZ: R7.2 U1.AE2(RESETFULLZ) ; off-sheet K2L_RESETFULLZ
K2L_RESETSTATZ: R4.2 U1.AE4(RESETSTATZ) ; off-sheet K2L_RESETSTATZ
K2L_RESETZ: R8.2 U1.AF3(RESETZ) ; off-sheet K2L_RESETZ
K2L_SYSCLKN: C2.2 ; off-sheet K2L_SYSCLKN
K2L_SYSCLKN_CS: C2.1 U1.AG29(SYSCLKN)
K2L_SYSCLKOUT: K2.1 R11.1 R11.2 U1.AF28(SYSCLKOUT) ; off-sheet K2L_SYSCLKOUT_RS  [also labelled K2L_SYSCLKOUT_RS]
K2L_SYSCLKP: C1.2 ; off-sheet K2L_SYSCLKP
K2L_SYSCLKP_CS: C1.1 U1.AF29(SYSCLKP)

Not connected (* = marked no-connect by the designer): U1 AE28(RSV005)* AE29(RSV004)* AH2(HOUT)*

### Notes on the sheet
- For schematic and layout recommendations and requirements see the K2L product page linked below.
- K2L Reset and Core Configuration
- TI 66AK2L06 Product Page <http://www.ti.com/lsds/ti/dsp/keystone_arm/66ak2lx/overview.page>
- K2L BOOTMODE and RESET pins mastered by Board Mangement Controller (microcontroller) not shown here.
- K2L RESETSTAT and BOOTCOMPLETE monitored by System Controller (microcontroller) not shown here.
- K2L CORESEL[2:0] and LRESET/NMIZ/LRESETNMIENZ signals all mastered by Board Management Controller (microcontroller) not shown here.
- CORECLKSEL[1:0] = 0b00
  Select SYSCLK as source for K2L Main PLL
- K2L Core and Peripheral PLL Reference Clock Inputs
- Place AC-coupling as close to BGA as possible.
- K2L PLLLOCK monitored by System Controller (microcontroller) not shown here.
- K2L SYSCLK sourced my LMK04828. When utilizing LVDS outputs of LMK04828 only AC-coupling is necessary.
- DDR3 controller reference clock solution not shown. Please see K2L EVM schematics.
- Not utilizing ALTCORECLK.  Pull-up/down resistor necessary to reserve off clock input.

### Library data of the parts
C1-C4 = C0603X5R0J104K030BC: CAP, CERM, 0.1 µF, 6.3 V, +/- 10%, X5R, 0201; Manufacturer: TDK; Polarized: N; CompType: Capacitor; Value: 0.1uF; U/M: EA; Cap_F: 0.0000001; Tolerance_%: 10; Value1: Unknown; VDC_V: 6.3; Value2: 6.3V; TaMin_C: -55; TaMax_C: 85
K1 K2 = TESTPOINT: TEST POINT.  No entry in BOM.
R1-R3 = CRCW04024K75FKED: RES, 4.75 k, 1%, 0.063 W, 0402; Manufacturer: Vishay-Dale; CompType: Resistor; Value: 4.75k; Res_ohm: 4750; Value_Code: 4k75; Tolerance_%: 1; Power_W: 0.063; Value2: 0.063W; VDC_V: 50; TempCo: 100 ppm/C; EIA_Code: E96; U/M: EA
R4-R10 R12-R14 = CRCW04021K00FKED: RES, 1.00 k, 1%, 0.063 W, 0402; Manufacturer: Vishay-Dale; CompType: Resistor; Value: 1.00k; Res_ohm: 1000; Value_Code: 1k00; Tolerance_%: 1; Power_W: 0.063; Value2: 0.063W; VDC_V: 50; TempCo: 100 ppm/C; EIA_Code: E96; U/M: EA
R11 = CRCW040210R0FKED: RES, 10.0, 1%, 0.063 W, 0402; Manufacturer: Vishay-Dale; CompType: Resistor; Value: 10.0; Res_ohm: 10; Value_Code: 10R0; Tolerance_%: 1; Power_W: 0.063; Value2: 0.063W; VDC_V: 50; TempCo: 100 ppm/C; EIA_Code: E96; U/M: EA
U1 = lamarr_soc_TCI6630K2L: as U1 on sheet k2l_soc_03_1

## Sheet k2l_soc_06.SchDoc
size 431 x 279 mm; Date: Not shown in title block; ApprovedBy: Not shown in title block; CheckedBy: Not shown in title block; Author: Not shown in title block; CompanyName: Not shown in title block; Engineer: Not shown in title block; Organization: Not shown in title block; Address1: Not shown in title block; Address2: Not shown in title block; Address3: Not shown in title block; Address4: Not shown in title block; DocumentNumber: 11; Revision: Use project parameter SCH_Rev; SheetNumber: 11; SheetTotal: 38; PageSetup: Record=PageOptions¦CenterHorizontal=True¦CenterVertical=True¦PrintScale=1.00¦XCorrection=1.00¦YCorrection=1.00¦PrintKind=0¦BorderSize=5000000¦LeftOffset=0¦BottomOffset=0¦Orientation=2¦PaperLength=1000¦PaperWidth=1000¦Scale=100¦PaperSource=15¦PrintQuality=600¦MediaType=1¦DitherType=10¦PaperKind=Letter¦PrintScaleMode=1
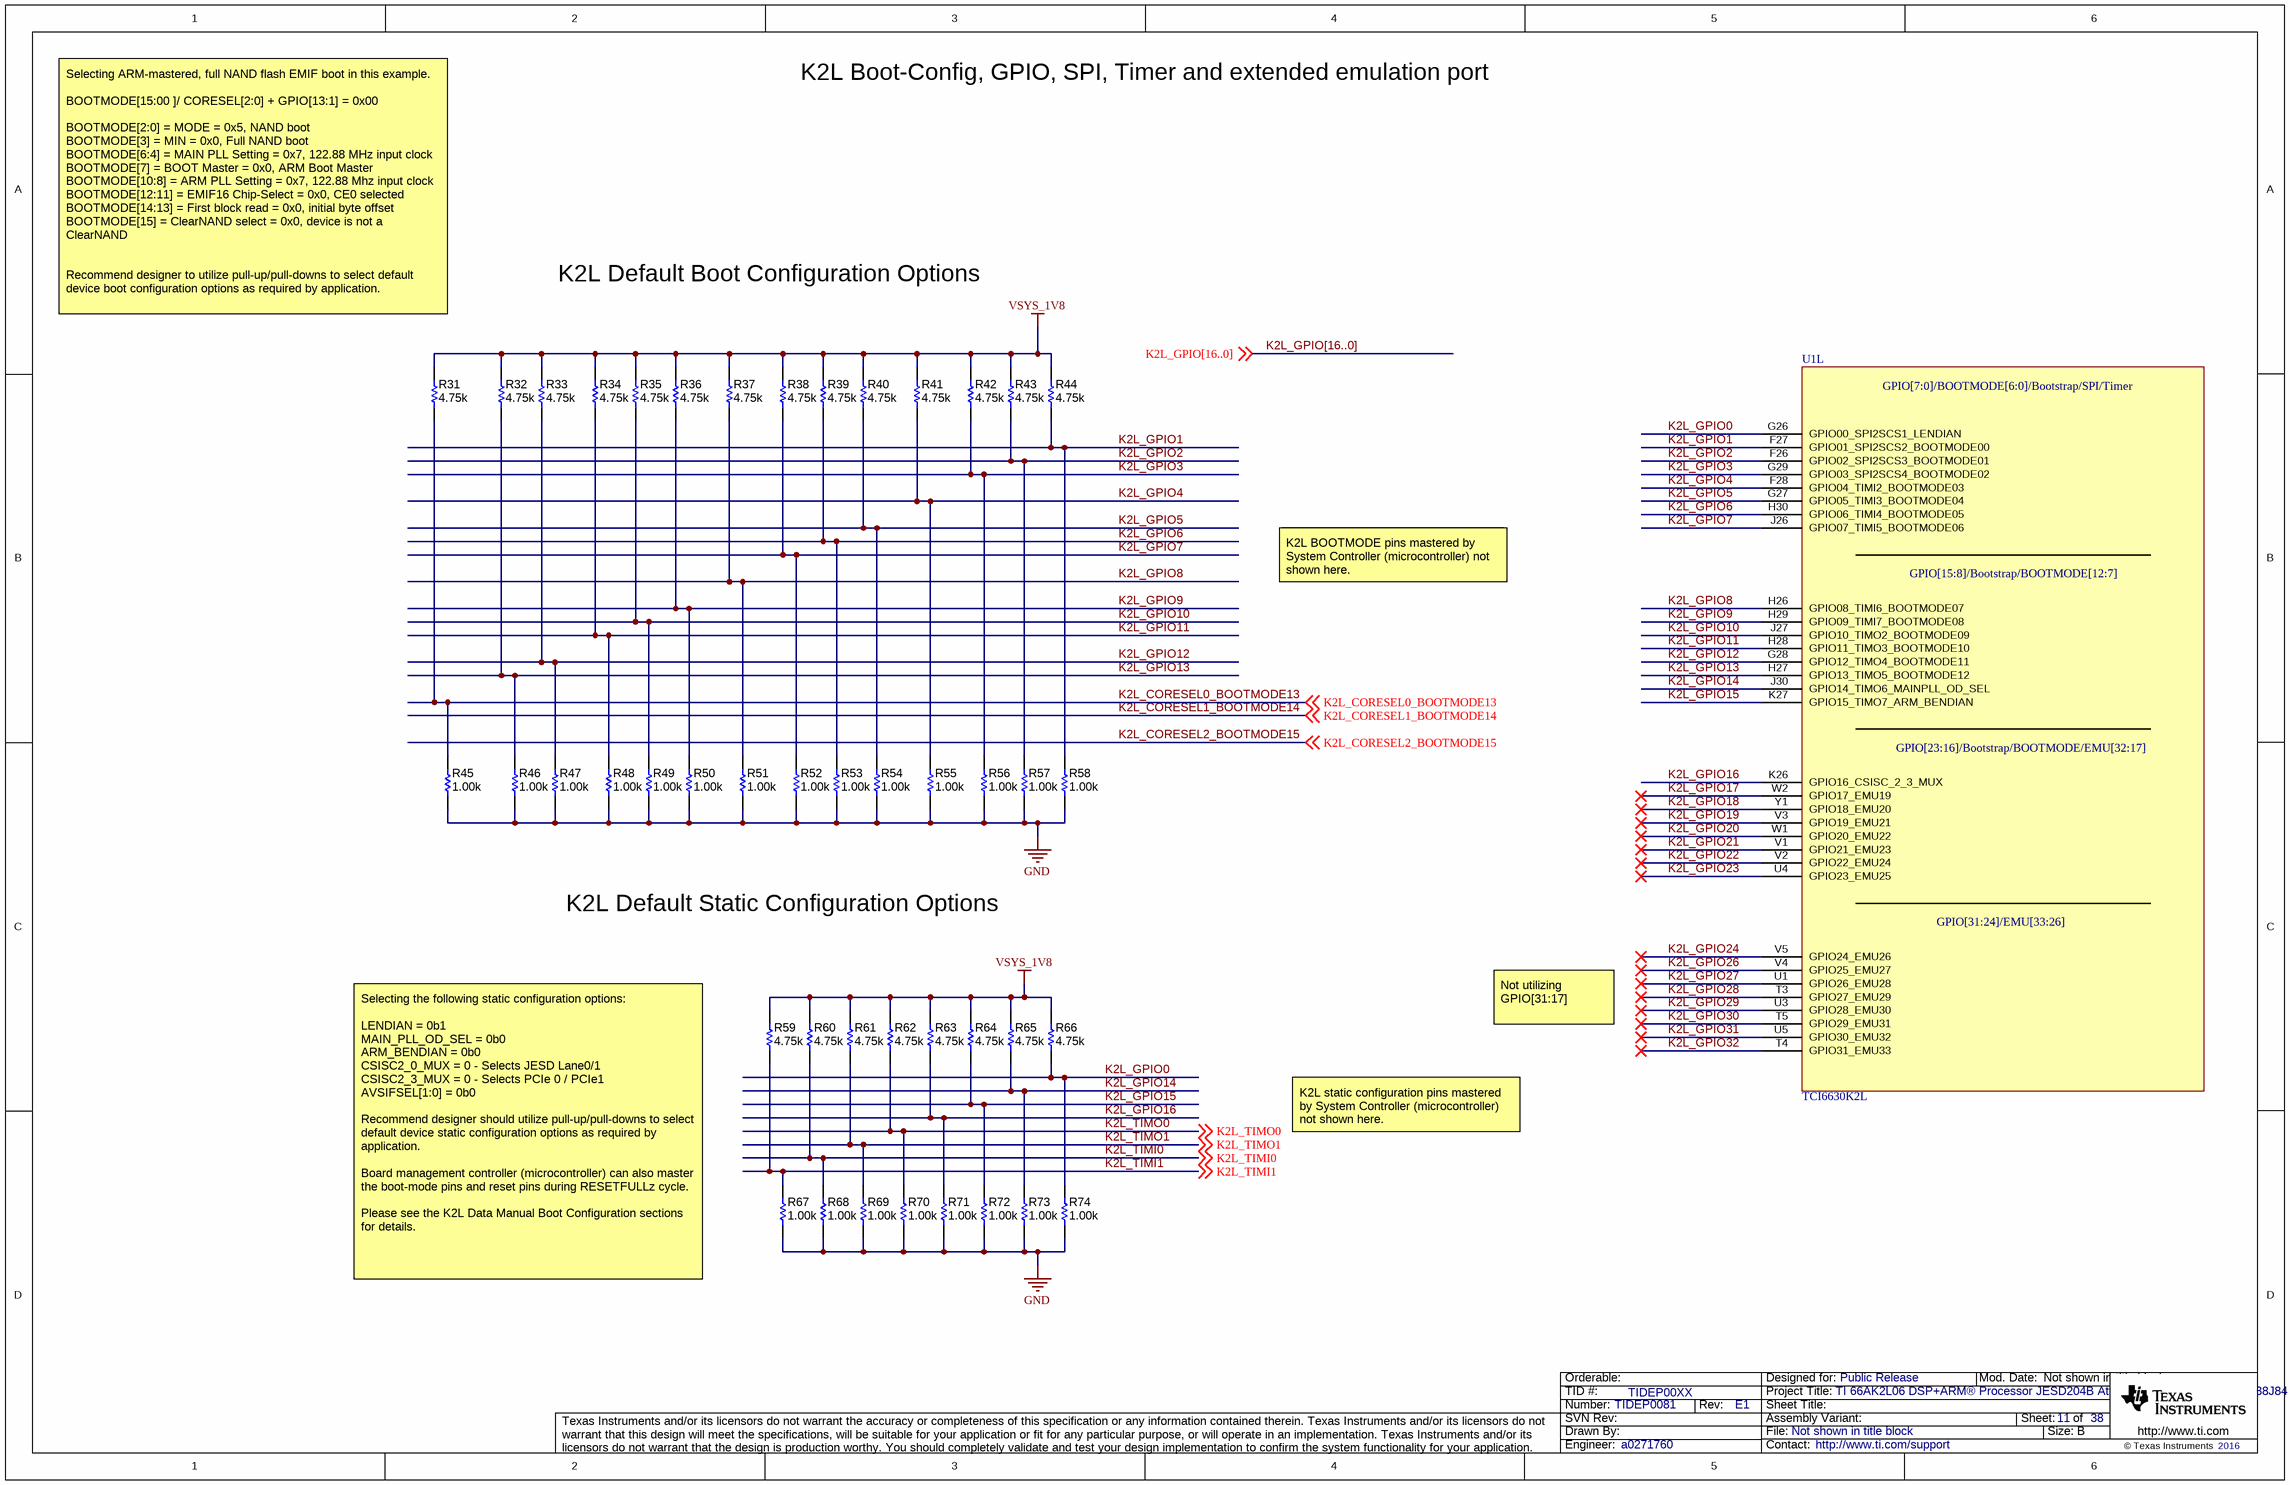
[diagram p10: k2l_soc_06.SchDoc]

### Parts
R31  ValueDisplayed: 4.75k  [0402]  (hidden comment: CRCW04024K75FKED)
R32  ValueDisplayed: 4.75k  [0402]  (hidden comment: CRCW04024K75FKED)
R33  ValueDisplayed: 4.75k  [0402]  (hidden comment: CRCW04024K75FKED)
R34  ValueDisplayed: 4.75k  [0402]  (hidden comment: CRCW04024K75FKED)
R35  ValueDisplayed: 4.75k  [0402]  (hidden comment: CRCW04024K75FKED)
R36  ValueDisplayed: 4.75k  [0402]  (hidden comment: CRCW04024K75FKED)
R37  ValueDisplayed: 4.75k  [0402]  (hidden comment: CRCW04024K75FKED)
R38  ValueDisplayed: 4.75k  [0402]  (hidden comment: CRCW04024K75FKED)
R39  ValueDisplayed: 4.75k  [0402]  (hidden comment: CRCW04024K75FKED)
R40  ValueDisplayed: 4.75k  [0402]  (hidden comment: CRCW04024K75FKED)
R41  ValueDisplayed: 4.75k  [0402]  (hidden comment: CRCW04024K75FKED)
R42  ValueDisplayed: 4.75k  [0402]  (hidden comment: CRCW04024K75FKED)
R43  ValueDisplayed: 4.75k  [0402]  (hidden comment: CRCW04024K75FKED)
R44  ValueDisplayed: 4.75k  [0402]  (hidden comment: CRCW04024K75FKED)
R45  ValueDisplayed: 1.00k  [0402]  (hidden comment: CRCW04021K00FKED)
R46  ValueDisplayed: 1.00k  [0402]  (hidden comment: CRCW04021K00FKED)
R47  ValueDisplayed: 1.00k  [0402]  (hidden comment: CRCW04021K00FKED)
R48  ValueDisplayed: 1.00k  [0402]  (hidden comment: CRCW04021K00FKED)
R49  ValueDisplayed: 1.00k  [0402]  (hidden comment: CRCW04021K00FKED)
R50  ValueDisplayed: 1.00k  [0402]  (hidden comment: CRCW04021K00FKED)
R51  ValueDisplayed: 1.00k  [0402]  (hidden comment: CRCW04021K00FKED)
R52  ValueDisplayed: 1.00k  [0402]  (hidden comment: CRCW04021K00FKED)
R53  ValueDisplayed: 1.00k  [0402]  (hidden comment: CRCW04021K00FKED)
R54  ValueDisplayed: 1.00k  [0402]  (hidden comment: CRCW04021K00FKED)
R55  ValueDisplayed: 1.00k  [0402]  (hidden comment: CRCW04021K00FKED)
R56  ValueDisplayed: 1.00k  [0402]  (hidden comment: CRCW04021K00FKED)
R57  ValueDisplayed: 1.00k  [0402]  (hidden comment: CRCW04021K00FKED)
R58  ValueDisplayed: 1.00k  [0402]  (hidden comment: CRCW04021K00FKED)
R59  ValueDisplayed: 4.75k  [0402]  (hidden comment: CRCW04024K75FKED)
R60  ValueDisplayed: 4.75k  [0402]  (hidden comment: CRCW04024K75FKED)
R61  ValueDisplayed: 4.75k  [0402]  (hidden comment: CRCW04024K75FKED)
R62  ValueDisplayed: 4.75k  [0402]  (hidden comment: CRCW04024K75FKED)
R63  ValueDisplayed: 4.75k  [0402]  (hidden comment: CRCW04024K75FKED)
R64  ValueDisplayed: 4.75k  [0402]  (hidden comment: CRCW04024K75FKED)
R65  ValueDisplayed: 4.75k  [0402]  (hidden comment: CRCW04024K75FKED)
R66  ValueDisplayed: 4.75k  [0402]  (hidden comment: CRCW04024K75FKED)
R67  ValueDisplayed: 1.00k  [0402]  (hidden comment: CRCW04021K00FKED)
R68  ValueDisplayed: 1.00k  [0402]  (hidden comment: CRCW04021K00FKED)
R69  ValueDisplayed: 1.00k  [0402]  (hidden comment: CRCW04021K00FKED)
R70  ValueDisplayed: 1.00k  [0402]  (hidden comment: CRCW04021K00FKED)
R71  ValueDisplayed: 1.00k  [0402]  (hidden comment: CRCW04021K00FKED)
R72  ValueDisplayed: 1.00k  [0402]  (hidden comment: CRCW04021K00FKED)
R73  ValueDisplayed: 1.00k  [0402]  (hidden comment: CRCW04021K00FKED)
R74  ValueDisplayed: 1.00k  [0402]  (hidden comment: CRCW04021K00FKED)
U1  TCI6630K2L  [BGA900C80P30X30_2500X2500X355]  (part L of 24)

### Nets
GND: R45.1 R46.1 R47.1 R48.1 R49.1 R50.1 R51.1 R52.1 R53.1 R54.1 R55.1 R56.1 R57.1 R58.1 R67.1 R68.1 R69.1 R70.1 R71.1 R72.1 R73.1 R74.1  [project net DAC_OUT0N_T1]
VSYS_1V8: R31.2 R32.2 R33.2 R34.2 R35.2 R36.2 R37.2 R38.2 R39.2 R40.2 R41.2 R42.2 R43.2 R44.2 R59.2 R60.2 R61.2 R62.2 R63.2 R64.2 R65.2 R66.2
K2L_CORESEL0_BOOTMODE13: R31.1 R45.2 ; off-sheet K2L_CORESEL0_BOOTMODE13
K2L_GPIO0: R66.1 R74.2 U1.G26(GPIO00_SPI2SCS1_LENDIAN)
K2L_GPIO1: R44.1 R58.2 U1.F27(GPIO01_SPI2SCS2_BOOTMODE00)
K2L_GPIO2: R43.1 R57.2 U1.F26(GPIO02_SPI2SCS3_BOOTMODE01)
K2L_GPIO3: R42.1 R56.2 U1.G29(GPIO03_SPI2SCS4_BOOTMODE02)
K2L_GPIO4: R41.1 R55.2 U1.F28(GPIO04_TIMI2_BOOTMODE03)
K2L_GPIO5: R40.1 R54.2 U1.G27(GPIO05_TIMI3_BOOTMODE04)
K2L_GPIO6: R39.1 R53.2 U1.H30(GPIO06_TIMI4_BOOTMODE05)
K2L_GPIO7: R38.1 R52.2 U1.J26(GPIO07_TIMI5_BOOTMODE06)
K2L_GPIO8: R37.1 R51.2 U1.H26(GPIO08_TIMI6_BOOTMODE07)
K2L_GPIO9: R36.1 R50.2 U1.H29(GPIO09_TIMI7_BOOTMODE08)
K2L_GPIO10: R35.1 R49.2 U1.J27(GPIO10_TIMO2_BOOTMODE09)
K2L_GPIO11: R34.1 R48.2 U1.H28(GPIO11_TIMO3_BOOTMODE10)
K2L_GPIO12: R33.1 R47.2 U1.G28(GPIO12_TIMO4_BOOTMODE11)
K2L_GPIO13: R32.1 R46.2 U1.H27(GPIO13_TIMO5_BOOTMODE12)
K2L_GPIO14: R65.1 R73.2 U1.J30(GPIO14_TIMO6_MAINPLL_OD_SEL)
K2L_GPIO15: R64.1 R72.2 U1.K27(GPIO15_TIMO7_ARM_BENDIAN)
K2L_GPIO16: R63.1 R71.2 U1.K26(GPIO16_CSISC_2_3_MUX)
K2L_GPIO17: U1.W2(GPIO17_EMU19)
K2L_GPIO18: U1.Y1(GPIO18_EMU20)
K2L_GPIO19: U1.V3(GPIO19_EMU21)
K2L_GPIO20: U1.W1(GPIO20_EMU22)
K2L_GPIO21: U1.V1(GPIO21_EMU23)
K2L_GPIO22: U1.V2(GPIO22_EMU24)
K2L_GPIO23: U1.U4(GPIO23_EMU25)
K2L_GPIO24: U1.V5(GPIO24_EMU26)
K2L_GPIO26: U1.V4(GPIO25_EMU27)
K2L_GPIO27: U1.U1(GPIO26_EMU28)
K2L_GPIO28: U1.T3(GPIO27_EMU29)
K2L_GPIO29: U1.U3(GPIO28_EMU30)
K2L_GPIO30: U1.T5(GPIO29_EMU31)
K2L_GPIO31: U1.U5(GPIO30_EMU32)
K2L_GPIO32: U1.T4(GPIO31_EMU33)
K2L_TIMI0: R60.1 R68.2 ; off-sheet K2L_TIMI0
K2L_TIMI1: R59.1 R67.2 ; off-sheet K2L_TIMI1
K2L_TIMO0: R62.1 R70.2 ; off-sheet K2L_TIMO0
K2L_TIMO1: R61.1 R69.2 ; off-sheet K2L_TIMO1

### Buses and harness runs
bus K2L_GPIO[16..0]

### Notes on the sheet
- K2L Boot-Config, GPIO, SPI, Timer and extended emulation port
- K2L Default Boot Configuration Options
- Selecting ARM-mastered, full NAND flash EMIF boot in this example.
  BOOTMODE[15:00 ]/ CORESEL[2:0] + GPIO[13:1] = 0x00
  BOOTMODE[2:0] = MODE = 0x5, NAND boot
  BOOTMODE[3] = MIN = 0x0, Full NAND boot
  BOOTMODE[6:4] = MAIN PLL Setting = 0x7, 122.88 MHz input clock
  BOOTMODE[7] = BOOT Master = 0x0, ARM Boot Master
  BOOTMODE[10:8] = ARM PLL Setting = 0x7, 122.88 Mhz input clock
  BOOTMODE[12:11] = EMIF16 Chip-Select = 0x0, CE0 selected
  BOOTMODE[14:13] = First block read = 0x0, initial byte offset
  BOOTMODE[15] = ClearNAND select = 0x0, device is not a ClearNAND
  Recommend designer to utilize pull-up/pull-downs to select default device boot configuration options as required by application.
  Board management controller (microcontroller) can also master the boot-mode pins and reset pins during RESETFULLz cycle.
- K2L BOOTMODE pins mastered by System Controller (microcontroller) not shown here.
- K2L Default Static Configuration Options
- Not utilizing GPIO[31:17]
- K2L static configuration pins mastered by System Controller (microcontroller) not shown here.
- Selecting the following static configuration options:
  LENDIAN = 0b1
  MAIN_PLL_OD_SEL = 0b0
  ARM_BENDIAN = 0b0
  CSISC2_0_MUX = 0 - Selects JESD Lane0/1
  CSISC2_3_MUX = 0 - Selects PCIe 0 / PCIe1
  AVSIFSEL[1:0] = 0b0
  Recommend designer should utilize pull-up/pull-downs to select default device static configuration options as required by application.
  Board management controller (microcontroller) can also master the boot-mode pins and reset pins during RESETFULLz cycle.
  Please see the K2L Data Manual Boot Configuration sections for details.

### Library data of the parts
R31-R44 R59-R66 = CRCW04024K75FKED: as R1-R3 on sheet k2l_soc_05
R45-R58 R67-R74 = CRCW04021K00FKED: as R4 on sheet k2l_soc_05
U1 = lamarr_soc_TCI6630K2L: as U1 on sheet k2l_soc_03_1

## Sheet k2l_soc_06_1.SchDoc
size 431 x 279 mm; Date: Not shown in title block; ApprovedBy: Not shown in title block; CheckedBy: Not shown in title block; Author: Not shown in title block; CompanyName: Not shown in title block; Engineer: Not shown in title block; Organization: Not shown in title block; Address1: Not shown in title block; Address2: Not shown in title block; Address3: Not shown in title block; Address4: Not shown in title block; DocumentNumber: 12; Revision: Use project parameter SCH_Rev; SheetNumber: 12; SheetTotal: 38; PageSetup: Record=PageOptions¦CenterHorizontal=True¦CenterVertical=True¦PrintScale=1.00¦XCorrection=1.00¦YCorrection=1.00¦PrintKind=0¦BorderSize=5000000¦LeftOffset=0¦BottomOffset=0¦Orientation=2¦PaperLength=1000¦PaperWidth=1000¦Scale=100¦PaperSource=15¦PrintQuality=600¦MediaType=1¦DitherType=10¦PaperKind=Letter¦PrintScaleMode=1
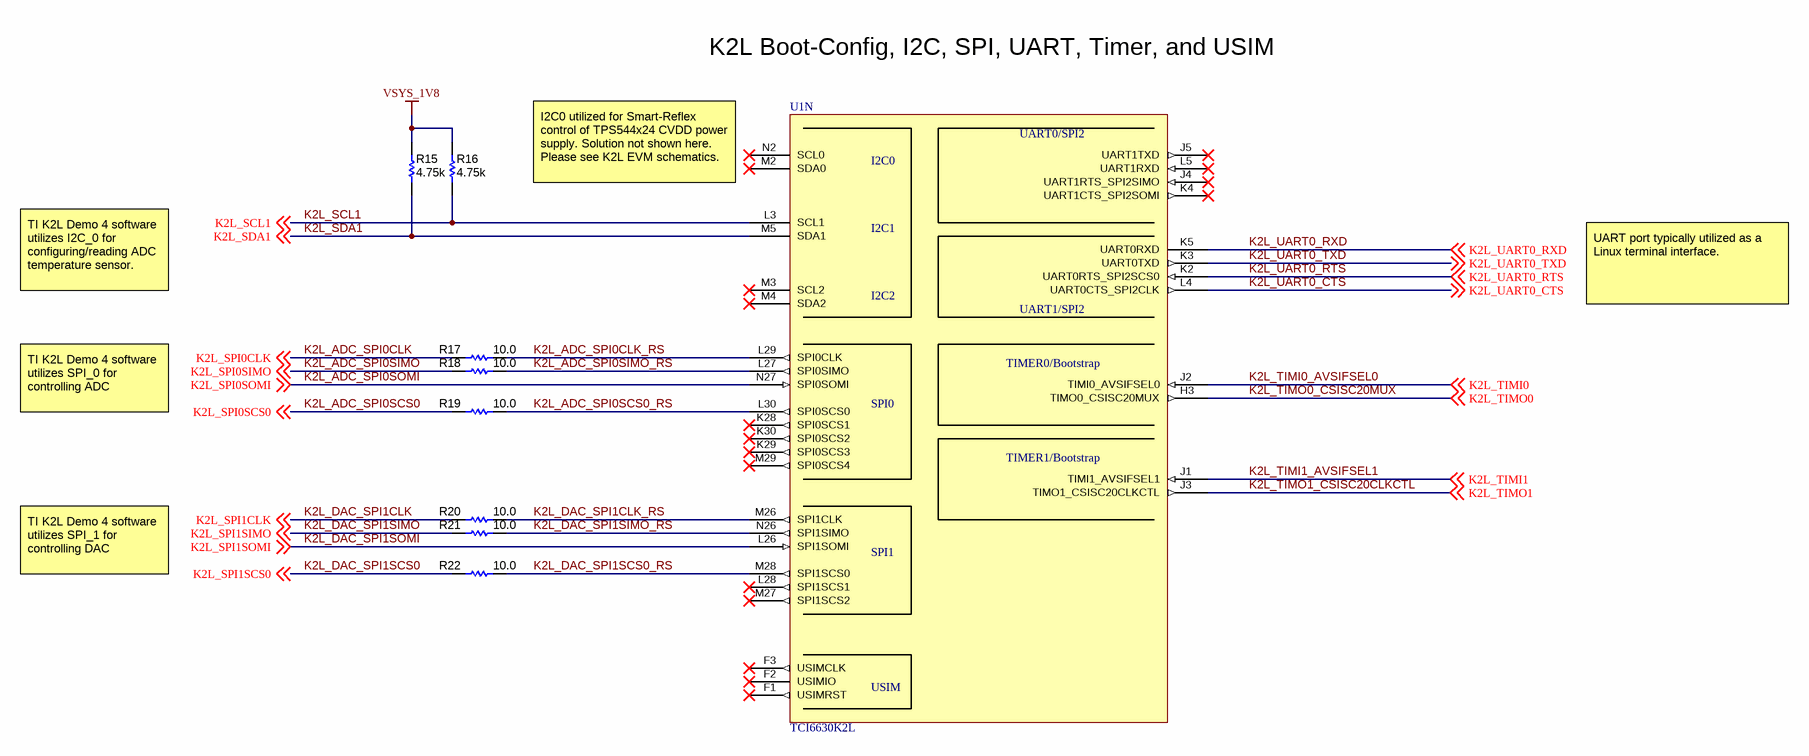
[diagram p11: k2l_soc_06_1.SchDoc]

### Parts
R15  ValueDisplayed: 4.75k  [0402]  (hidden comment: CRCW04024K75FKED)
R16  ValueDisplayed: 4.75k  [0402]  (hidden comment: CRCW04024K75FKED)
R17  ValueDisplayed: 10.0  [0402]  (hidden comment: CRCW040210R0FKED)
R18  ValueDisplayed: 10.0  [0402]  (hidden comment: CRCW040210R0FKED)
R19  ValueDisplayed: 10.0  [0402]  (hidden comment: CRCW040210R0FKED)
R20  ValueDisplayed: 10.0  [0402]  (hidden comment: CRCW040210R0FKED)
R21  ValueDisplayed: 10.0  [0402]  (hidden comment: CRCW040210R0FKED)
R22  ValueDisplayed: 10.0  [0402]  (hidden comment: CRCW040210R0FKED)
U1  TCI6630K2L  [BGA900C80P30X30_2500X2500X355]  (part N of 24)

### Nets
VSYS_1V8: R15.2 R16.2
K2L_ADC_SPI0CLK: R17.1 ; off-sheet K2L_SPI0CLK  [also labelled K2L_SPI0CLK]
K2L_ADC_SPI0CLK_RS: R17.2 U1.L29(SPI0CLK)
K2L_ADC_SPI0SCS0: R19.1 ; off-sheet K2L_SPI0SCS0  [also labelled K2L_SPI0SCS0]
K2L_ADC_SPI0SCS0_RS: R19.2 U1.L30(SPI0SCS0)
K2L_ADC_SPI0SIMO: R18.1 ; off-sheet K2L_SPI0SIMO  [also labelled K2L_SPI0SIMO]
K2L_ADC_SPI0SIMO_RS: R18.2 U1.L27(SPI0SIMO)
K2L_ADC_SPI0SOMI: U1.N27(SPI0SOMI) ; off-sheet K2L_SPI0SOMI  [also labelled K2L_SPI0SOMI]
K2L_DAC_SPI1CLK: R20.1 ; off-sheet K2L_SPI1CLK  [also labelled K2L_SPI1CLK]
K2L_DAC_SPI1CLK_RS: R20.2 U1.M26(SPI1CLK)
K2L_DAC_SPI1SCS0: R22.1 ; off-sheet K2L_SPI1SCS0  [also labelled K2L_SPI1SCS0]
K2L_DAC_SPI1SCS0_RS: R22.2 U1.M28(SPI1SCS0)
K2L_DAC_SPI1SIMO: R21.1 ; off-sheet K2L_SPI1SIMO  [also labelled K2L_SPI1SIMO]
K2L_DAC_SPI1SIMO_RS: R21.2 U1.N26(SPI1SIMO)
K2L_DAC_SPI1SOMI: U1.L26(SPI1SOMI) ; off-sheet K2L_SPI1SOMI  [also labelled K2L_SPI1SOMI]
K2L_SCL1: R16.1 U1.L3(SCL1) ; off-sheet K2L_SCL1
K2L_SDA1: R15.1 U1.M5(SDA1) ; off-sheet K2L_SDA1
K2L_TIMI0: U1.J2(TIMI0_AVSIFSEL0) ; off-sheet K2L_TIMI0  [also labelled K2L_TIMI0_AVSIFSEL0]
K2L_TIMI1: U1.J1(TIMI1_AVSIFSEL1) ; off-sheet K2L_TIMI1  [also labelled K2L_TIMI1_AVSIFSEL1]
K2L_TIMO0: U1.H3(TIMO0_CSISC20MUX) ; off-sheet K2L_TIMO0  [also labelled K2L_TIMO0_CSISC20MUX]
K2L_TIMO1: U1.J3(TIMO1_CSISC20CLKCTL) ; off-sheet K2L_TIMO1  [also labelled K2L_TIMO1_CSISC20CLKCTL]
K2L_UART0_CTS: U1.L4(UART0CTS_SPI2CLK) ; off-sheet K2L_UART0_CTS
K2L_UART0_RTS: U1.K2(UART0RTS_SPI2SCS0) ; off-sheet K2L_UART0_RTS
K2L_UART0_RXD: U1.K5(UART0RXD) ; off-sheet K2L_UART0_RXD
K2L_UART0_TXD: U1.K3(UART0TXD) ; off-sheet K2L_UART0_TXD

Not connected (* = marked no-connect by the designer): U1 F1(USIMRST)* F2(USIMIO)* F3(USIMCLK)* J4(UART1RTS_SPI2SIMO)* J5(UART1TXD)* K4(UART1CTS_SPI2SOMI)* K28(SPI0SCS1)* K29(SPI0SCS3)* K30(SPI0SCS2)* L5(UART1RXD)* L28(SPI1SCS1)* M2(SDA0)* M3(SCL2)* M4(SDA2)* M27(SPI1SCS2)* M29(SPI0SCS4)* N2(SCL0)*

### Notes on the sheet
- K2L Boot-Config, I2C, SPI, UART, Timer, and USIM
- I2C0 utilized for Smart-Reflex control of TPS544x24 CVDD power supply. Solution not shown here. Please see K2L EVM schematics.
- TI K2L Demo 4 software utilizes I2C_0 for configuring/reading ADC temperature sensor.
- UART port typically utilized as a Linux terminal interface.
- TI K2L Demo 4 software utilizes SPI_0 for controlling ADC
- TI K2L Demo 4 software utilizes SPI_1 for controlling DAC

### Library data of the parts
R15 R16 = CRCW04024K75FKED: as R1-R3 on sheet k2l_soc_05
R17-R22 = CRCW040210R0FKED: as R11 on sheet k2l_soc_05
U1 = lamarr_soc_TCI6630K2L: as U1 on sheet k2l_soc_03_1

## Sheet k2l_soc_07.SchDoc
size 431 x 279 mm; Date: Not shown in title block; ApprovedBy: Not shown in title block; CheckedBy: Not shown in title block; Author: Not shown in title block; CompanyName: Not shown in title block; Engineer: Not shown in title block; Organization: Not shown in title block; Address1: Not shown in title block; Address2: Not shown in title block; Address3: Not shown in title block; Address4: Not shown in title block; DocumentNumber: 13; Revision: Use project parameter SCH_Rev; SheetNumber: 13; SheetTotal: 38; PageSetup: Record=PageOptions¦CenterHorizontal=True¦CenterVertical=True¦PrintScale=1.00¦XCorrection=1.00¦YCorrection=1.00¦PrintKind=0¦BorderSize=5000000¦LeftOffset=0¦BottomOffset=0¦Orientation=2¦PaperLength=1000¦PaperWidth=1000¦Scale=100¦PaperSource=15¦PrintQuality=600¦MediaType=1¦DitherType=10¦PaperKind=Letter¦PrintScaleMode=1
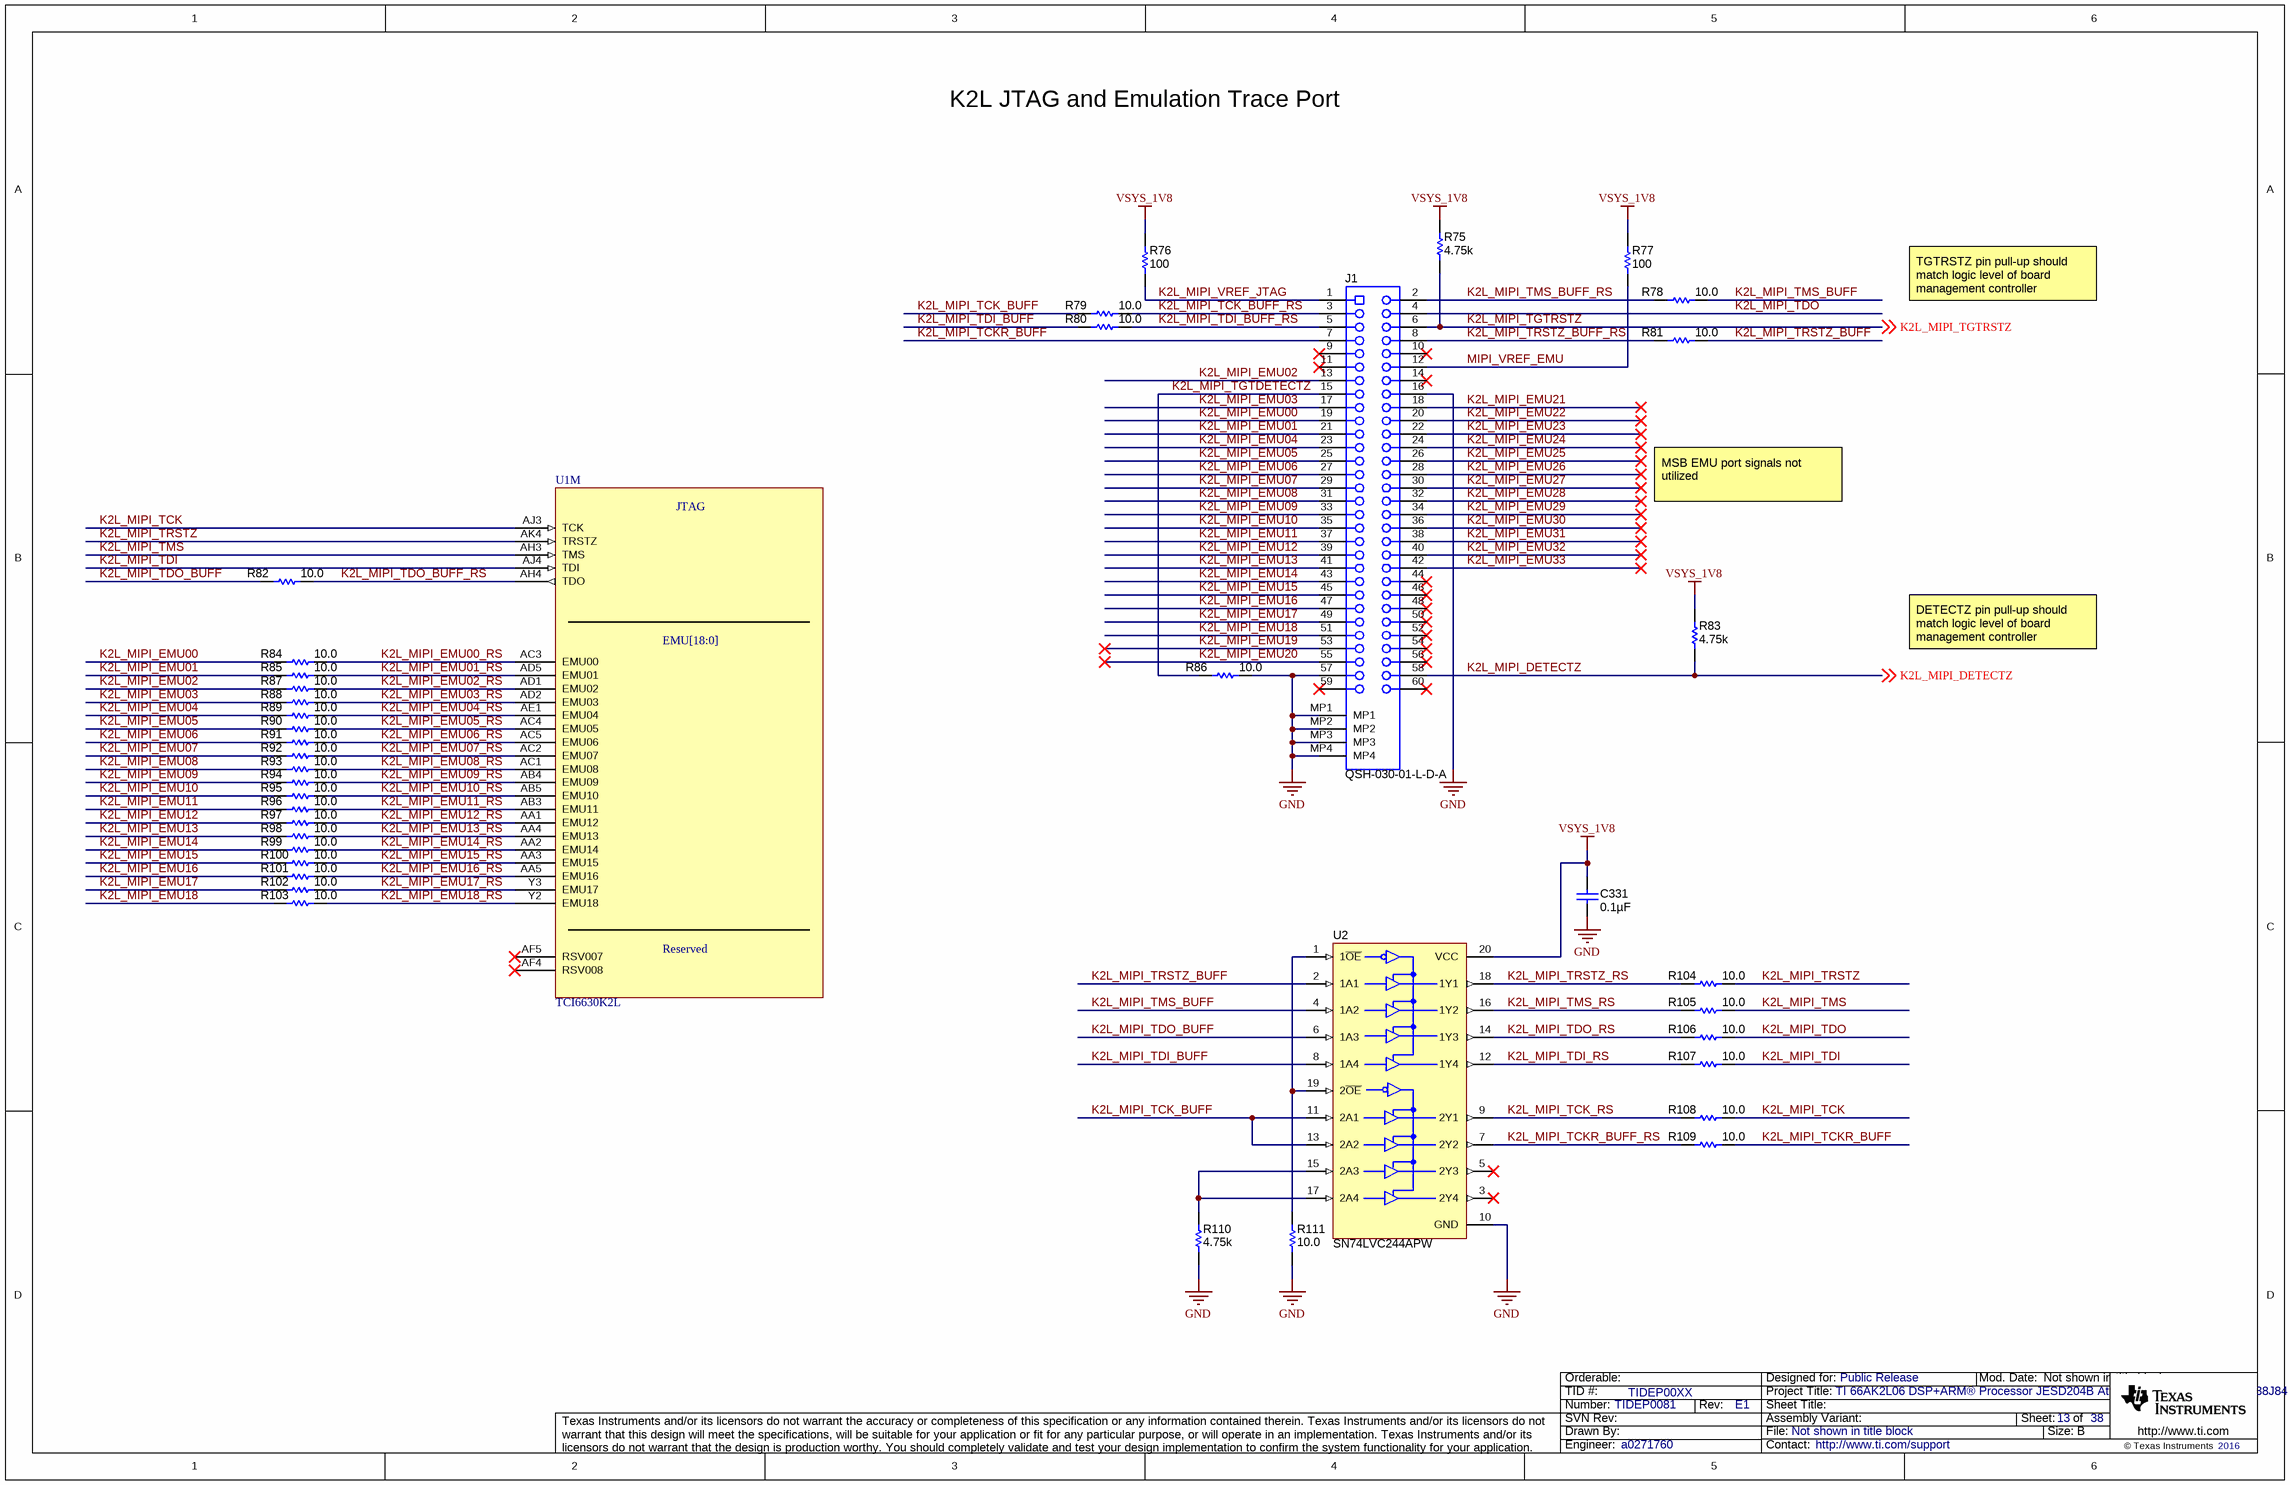
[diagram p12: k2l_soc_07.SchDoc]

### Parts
C331  ValueDisplayed: 0.1µF  [0402]  (hidden comment: GRM152B30J104KE19)
J1  QSH-030-01-L-D-A  [Samtec_QSH-030-01-X-D-A]
R75  ValueDisplayed: 4.75k  [0402]  (hidden comment: CRCW04024K75FKED)
R76  ValueDisplayed: 100  [0402]  (hidden comment: CRCW0402100RFKED)
R77  ValueDisplayed: 100  [0402]  (hidden comment: CRCW0402100RFKED)
R78  ValueDisplayed: 10.0  [0402]  (hidden comment: CRCW040210R0FKED)
R79  ValueDisplayed: 10.0  [0402]  (hidden comment: CRCW040210R0FKED)
R80  ValueDisplayed: 10.0  [0402]  (hidden comment: CRCW040210R0FKED)
R81  ValueDisplayed: 10.0  [0402]  (hidden comment: CRCW040210R0FKED)
R82  ValueDisplayed: 10.0  [0402]  (hidden comment: CRCW040210R0FKED)
R83  ValueDisplayed: 4.75k  [0402]  (hidden comment: CRCW04024K75FKED)
R84  ValueDisplayed: 10.0  [0402]  (hidden comment: CRCW040210R0FKED)
R85  ValueDisplayed: 10.0  [0402]  (hidden comment: CRCW040210R0FKED)
R86  ValueDisplayed: 10.0  [0402]  (hidden comment: CRCW040210R0FKED)
R87  ValueDisplayed: 10.0  [0402]  (hidden comment: CRCW040210R0FKED)
R88  ValueDisplayed: 10.0  [0402]  (hidden comment: CRCW040210R0FKED)
R89  ValueDisplayed: 10.0  [0402]  (hidden comment: CRCW040210R0FKED)
R90  ValueDisplayed: 10.0  [0402]  (hidden comment: CRCW040210R0FKED)
R91  ValueDisplayed: 10.0  [0402]  (hidden comment: CRCW040210R0FKED)
R92  ValueDisplayed: 10.0  [0402]  (hidden comment: CRCW040210R0FKED)
R93  ValueDisplayed: 10.0  [0402]  (hidden comment: CRCW040210R0FKED)
R94  ValueDisplayed: 10.0  [0402]  (hidden comment: CRCW040210R0FKED)
R95  ValueDisplayed: 10.0  [0402]  (hidden comment: CRCW040210R0FKED)
R96  ValueDisplayed: 10.0  [0402]  (hidden comment: CRCW040210R0FKED)
R97  ValueDisplayed: 10.0  [0402]  (hidden comment: CRCW040210R0FKED)
R98  ValueDisplayed: 10.0  [0402]  (hidden comment: CRCW040210R0FKED)
R99  ValueDisplayed: 10.0  [0402]  (hidden comment: CRCW040210R0FKED)
R100  ValueDisplayed: 10.0  [0402]  (hidden comment: CRCW040210R0FKED)
R101  ValueDisplayed: 10.0  [0402]  (hidden comment: CRCW040210R0FKED)
R102  ValueDisplayed: 10.0  [0402]  (hidden comment: CRCW040210R0FKED)
R103  ValueDisplayed: 10.0  [0402]  (hidden comment: CRCW040210R0FKED)
R104  ValueDisplayed: 10.0  [0402]  (hidden comment: CRCW040210R0FKED)
R105  ValueDisplayed: 10.0  [0402]  (hidden comment: CRCW040210R0FKED)
R106  ValueDisplayed: 10.0  [0402]  (hidden comment: CRCW040210R0FKED)
R107  ValueDisplayed: 10.0  [0402]  (hidden comment: CRCW040210R0FKED)
R108  ValueDisplayed: 10.0  [0402]  (hidden comment: CRCW040210R0FKED)
R109  ValueDisplayed: 10.0  [0402]  (hidden comment: CRCW040210R0FKED)
R110  ValueDisplayed: 4.75k  [0402]  (hidden comment: CRCW04024K75FKED)
R111  ValueDisplayed: 10.0  [0402]  (hidden comment: CRCW040210R0FKED)
U1  TCI6630K2L  [BGA900C80P30X30_2500X2500X355]  (part M of 24)
U2  SN74LVC244APW  [PW0020A_N]

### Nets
GND: C331.2 J1.16 J1.57 J1.MP1 J1.MP2 J1.MP3 J1.MP4 R86.2 R110.1 R111.1 U2.10(GND)  [project net DAC_OUT0N_T1]
VSYS_1V8: C331.1 R75.2 R76.2 R77.2 R83.2 U2.20(VCC)
K2L_MIPI_DETECTZ: J1.58 R83.1 ; off-sheet K2L_MIPI_DETECTZ
K2L_MIPI_EMU00: J1.19 R84.1
K2L_MIPI_EMU00_RS: R84.2 U1.AC3(EMU00)
K2L_MIPI_EMU01: J1.21 R85.1
K2L_MIPI_EMU01_RS: R85.2 U1.AD5(EMU01)
K2L_MIPI_EMU02: J1.13 R87.1
K2L_MIPI_EMU02_RS: R87.2 U1.AD1(EMU02)
K2L_MIPI_EMU03: J1.17 R88.1
K2L_MIPI_EMU03_RS: R88.2 U1.AD2(EMU03)
K2L_MIPI_EMU04: J1.23 R89.1
K2L_MIPI_EMU04_RS: R89.2 U1.AE1(EMU04)
K2L_MIPI_EMU05: J1.25 R90.1
K2L_MIPI_EMU05_RS: R90.2 U1.AC4(EMU05)
K2L_MIPI_EMU06: J1.27 R91.1
K2L_MIPI_EMU06_RS: R91.2 U1.AC5(EMU06)
K2L_MIPI_EMU07: J1.29 R92.1
K2L_MIPI_EMU07_RS: R92.2 U1.AC2(EMU07)
K2L_MIPI_EMU08: J1.31 R93.1
K2L_MIPI_EMU08_RS: R93.2 U1.AC1(EMU08)
K2L_MIPI_EMU09: J1.33 R94.1
K2L_MIPI_EMU09_RS: R94.2 U1.AB4(EMU09)
K2L_MIPI_EMU10: J1.35 R95.1
K2L_MIPI_EMU10_RS: R95.2 U1.AB5(EMU10)
K2L_MIPI_EMU11: J1.37 R96.1
K2L_MIPI_EMU11_RS: R96.2 U1.AB3(EMU11)
K2L_MIPI_EMU12: J1.39 R97.1
K2L_MIPI_EMU12_RS: R97.2 U1.AA1(EMU12)
K2L_MIPI_EMU13: J1.41 R98.1
K2L_MIPI_EMU13_RS: R98.2 U1.AA4(EMU13)
K2L_MIPI_EMU14: J1.43 R99.1
K2L_MIPI_EMU14_RS: R99.2 U1.AA2(EMU14)
K2L_MIPI_EMU15: J1.45 R100.1
K2L_MIPI_EMU15_RS: R100.2 U1.AA3(EMU15)
K2L_MIPI_EMU16: J1.47 R101.1
K2L_MIPI_EMU16_RS: R101.2 U1.AA5(EMU16)
K2L_MIPI_EMU17: J1.49 R102.1
K2L_MIPI_EMU17_RS: R102.2 U1.Y3(EMU17)
K2L_MIPI_EMU18: J1.51 R103.1
K2L_MIPI_EMU18_RS: R103.2 U1.Y2(EMU18)
K2L_MIPI_EMU19: J1.53
K2L_MIPI_EMU20: J1.55
K2L_MIPI_EMU21: J1.18
K2L_MIPI_EMU22: J1.20
K2L_MIPI_EMU23: J1.22
K2L_MIPI_EMU24: J1.24
K2L_MIPI_EMU25: J1.26
K2L_MIPI_EMU26: J1.28
K2L_MIPI_EMU27: J1.30
K2L_MIPI_EMU28: J1.32
K2L_MIPI_EMU29: J1.34
K2L_MIPI_EMU30: J1.36
K2L_MIPI_EMU31: J1.38
K2L_MIPI_EMU32: J1.40
K2L_MIPI_EMU33: J1.42
K2L_MIPI_TCK: R108.2 U1.AJ3(TCK)
K2L_MIPI_TCK_BUFF: R79.1 U2.11(2A1) U2.13(2A2)
K2L_MIPI_TCK_BUFF_RS: J1.3 R79.2
K2L_MIPI_TCK_RS: R108.1 U2.9(2Y1)
K2L_MIPI_TCKR_BUFF: J1.7 R109.2
K2L_MIPI_TCKR_BUFF_RS: R109.1 U2.7(2Y2)
K2L_MIPI_TDI: R107.2 U1.AJ4(TDI)
K2L_MIPI_TDI_BUFF: R80.1 U2.8(1A4)
K2L_MIPI_TDI_BUFF_RS: J1.5 R80.2
K2L_MIPI_TDI_RS: R107.1 U2.12(1Y4)
K2L_MIPI_TDO: J1.4 R106.2
K2L_MIPI_TDO_BUFF: R82.1 U2.6(1A3)
K2L_MIPI_TDO_BUFF_RS: R82.2 U1.AH4(TDO)
K2L_MIPI_TDO_RS: R106.1 U2.14(1Y3)
K2L_MIPI_TGTDETECTZ: J1.15 R86.1
K2L_MIPI_TGTRSTZ: J1.6 R75.1 ; off-sheet K2L_MIPI_TGTRSTZ
K2L_MIPI_TMS: R105.2 U1.AH3(TMS)
K2L_MIPI_TMS_BUFF: R78.2 U2.4(1A2)
K2L_MIPI_TMS_BUFF_RS: J1.2 R78.1
K2L_MIPI_TMS_RS: R105.1 U2.16(1Y2)
K2L_MIPI_TRSTZ: R104.2 U1.AK4(TRSTZ)
K2L_MIPI_TRSTZ_BUFF: R81.2 U2.2(1A1)
K2L_MIPI_TRSTZ_BUFF_RS: J1.8 R81.1
K2L_MIPI_TRSTZ_RS: R104.1 U2.18(1Y1)
K2L_MIPI_VREF_JTAG: J1.1 R76.1
MIPI_VREF_EMU: J1.12 R77.1
NetR110_2: R110.2 U2.15(2A3) U2.17(2A4)
NetR111_2: R111.2 U2.1(1~{OE}) U2.19(2~{OE})

Not connected (* = marked no-connect by the designer): J1 9* 10* 11* 14* 44* 46* 48* 50* 52* 54* 56* 59* 60*; U1 AF4(RSV008)* AF5(RSV007)*; U2 3(2Y4)* 5(2Y3)*

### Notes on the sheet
- K2L JTAG and Emulation Trace Port
- TGTRSTZ pin pull-up should match logic level of board management controller
- MSB EMU port signals not utilized
- DETECTZ pin pull-up should match logic level of board management controller

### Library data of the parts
C331 = GRM152B30J104KE19: CAP, CERM, 0.1 µF, 6.3 V, +/- 10%, B, 0402; Manufacturer: MuRata; Polarized: N; CompType: Capacitor; Value: 0.1uF; U/M: EA; Cap_F: 0.0000001; Tolerance_%: 10; Value1: Unknown; VDC_V: 6.3; Value2: 6.3V; TaMin_C: -25; TaMax_C: 85
J1 = QSH-030-01-L-D-A: Receptacle, 0.5 mm, 30x2, Gold, TH; Manufacturer: Samtec; SymbolCreator: Altium; U/M: EA
R75 R83 R110 = CRCW04024K75FKED: as R1-R3 on sheet k2l_soc_05
R76 R77 = CRCW0402100RFKED: RES, 100, 1%, 0.063 W, 0402; Manufacturer: Vishay-Dale; CompType: Resistor; Value: 100; Value_Code: 100R; Tolerance_%: 1; Power_W: 0.063; Value2: 0.063W; VDC_V: 50; TempCo: 100 ppm/C; EIA_Code: E96; U/M: EA
R78-R82 R84-R109 R111 = CRCW040210R0FKED: as R11 on sheet k2l_soc_05
U1 = lamarr_soc_TCI6630K2L: as U1 on sheet k2l_soc_03_1
U2 = SN74LVC244APW: OCTAL BUFFER/DRIVER WITH 3-STATE OUTPUTS, PW0020A; Manufacturer: Texas Instruments; SymbolVersion: use current date i.e. 2008-05-20; SymbolCreator: Use a-id; CompType: IC; U/M: EA

## Sheet k2l_soc_08.SchDoc
size 431 x 279 mm; Date: Not shown in title block; ApprovedBy: Not shown in title block; CheckedBy: Not shown in title block; Author: Not shown in title block; CompanyName: Not shown in title block; Engineer: Not shown in title block; Organization: Not shown in title block; Address1: Not shown in title block; Address2: Not shown in title block; Address3: Not shown in title block; Address4: Not shown in title block; DocumentNumber: 14; Revision: Use project parameter SCH_Rev; SheetNumber: 14; SheetTotal: 38; PageSetup: Record=PageOptions¦CenterHorizontal=True¦CenterVertical=True¦PrintScale=1.00¦XCorrection=1.00¦YCorrection=1.00¦PrintKind=0¦BorderSize=5000000¦LeftOffset=0¦BottomOffset=0¦Orientation=2¦PaperLength=1000¦PaperWidth=1000¦Scale=100¦PaperSource=15¦PrintQuality=600¦MediaType=1¦DitherType=10¦PaperKind=Letter¦PrintScaleMode=1
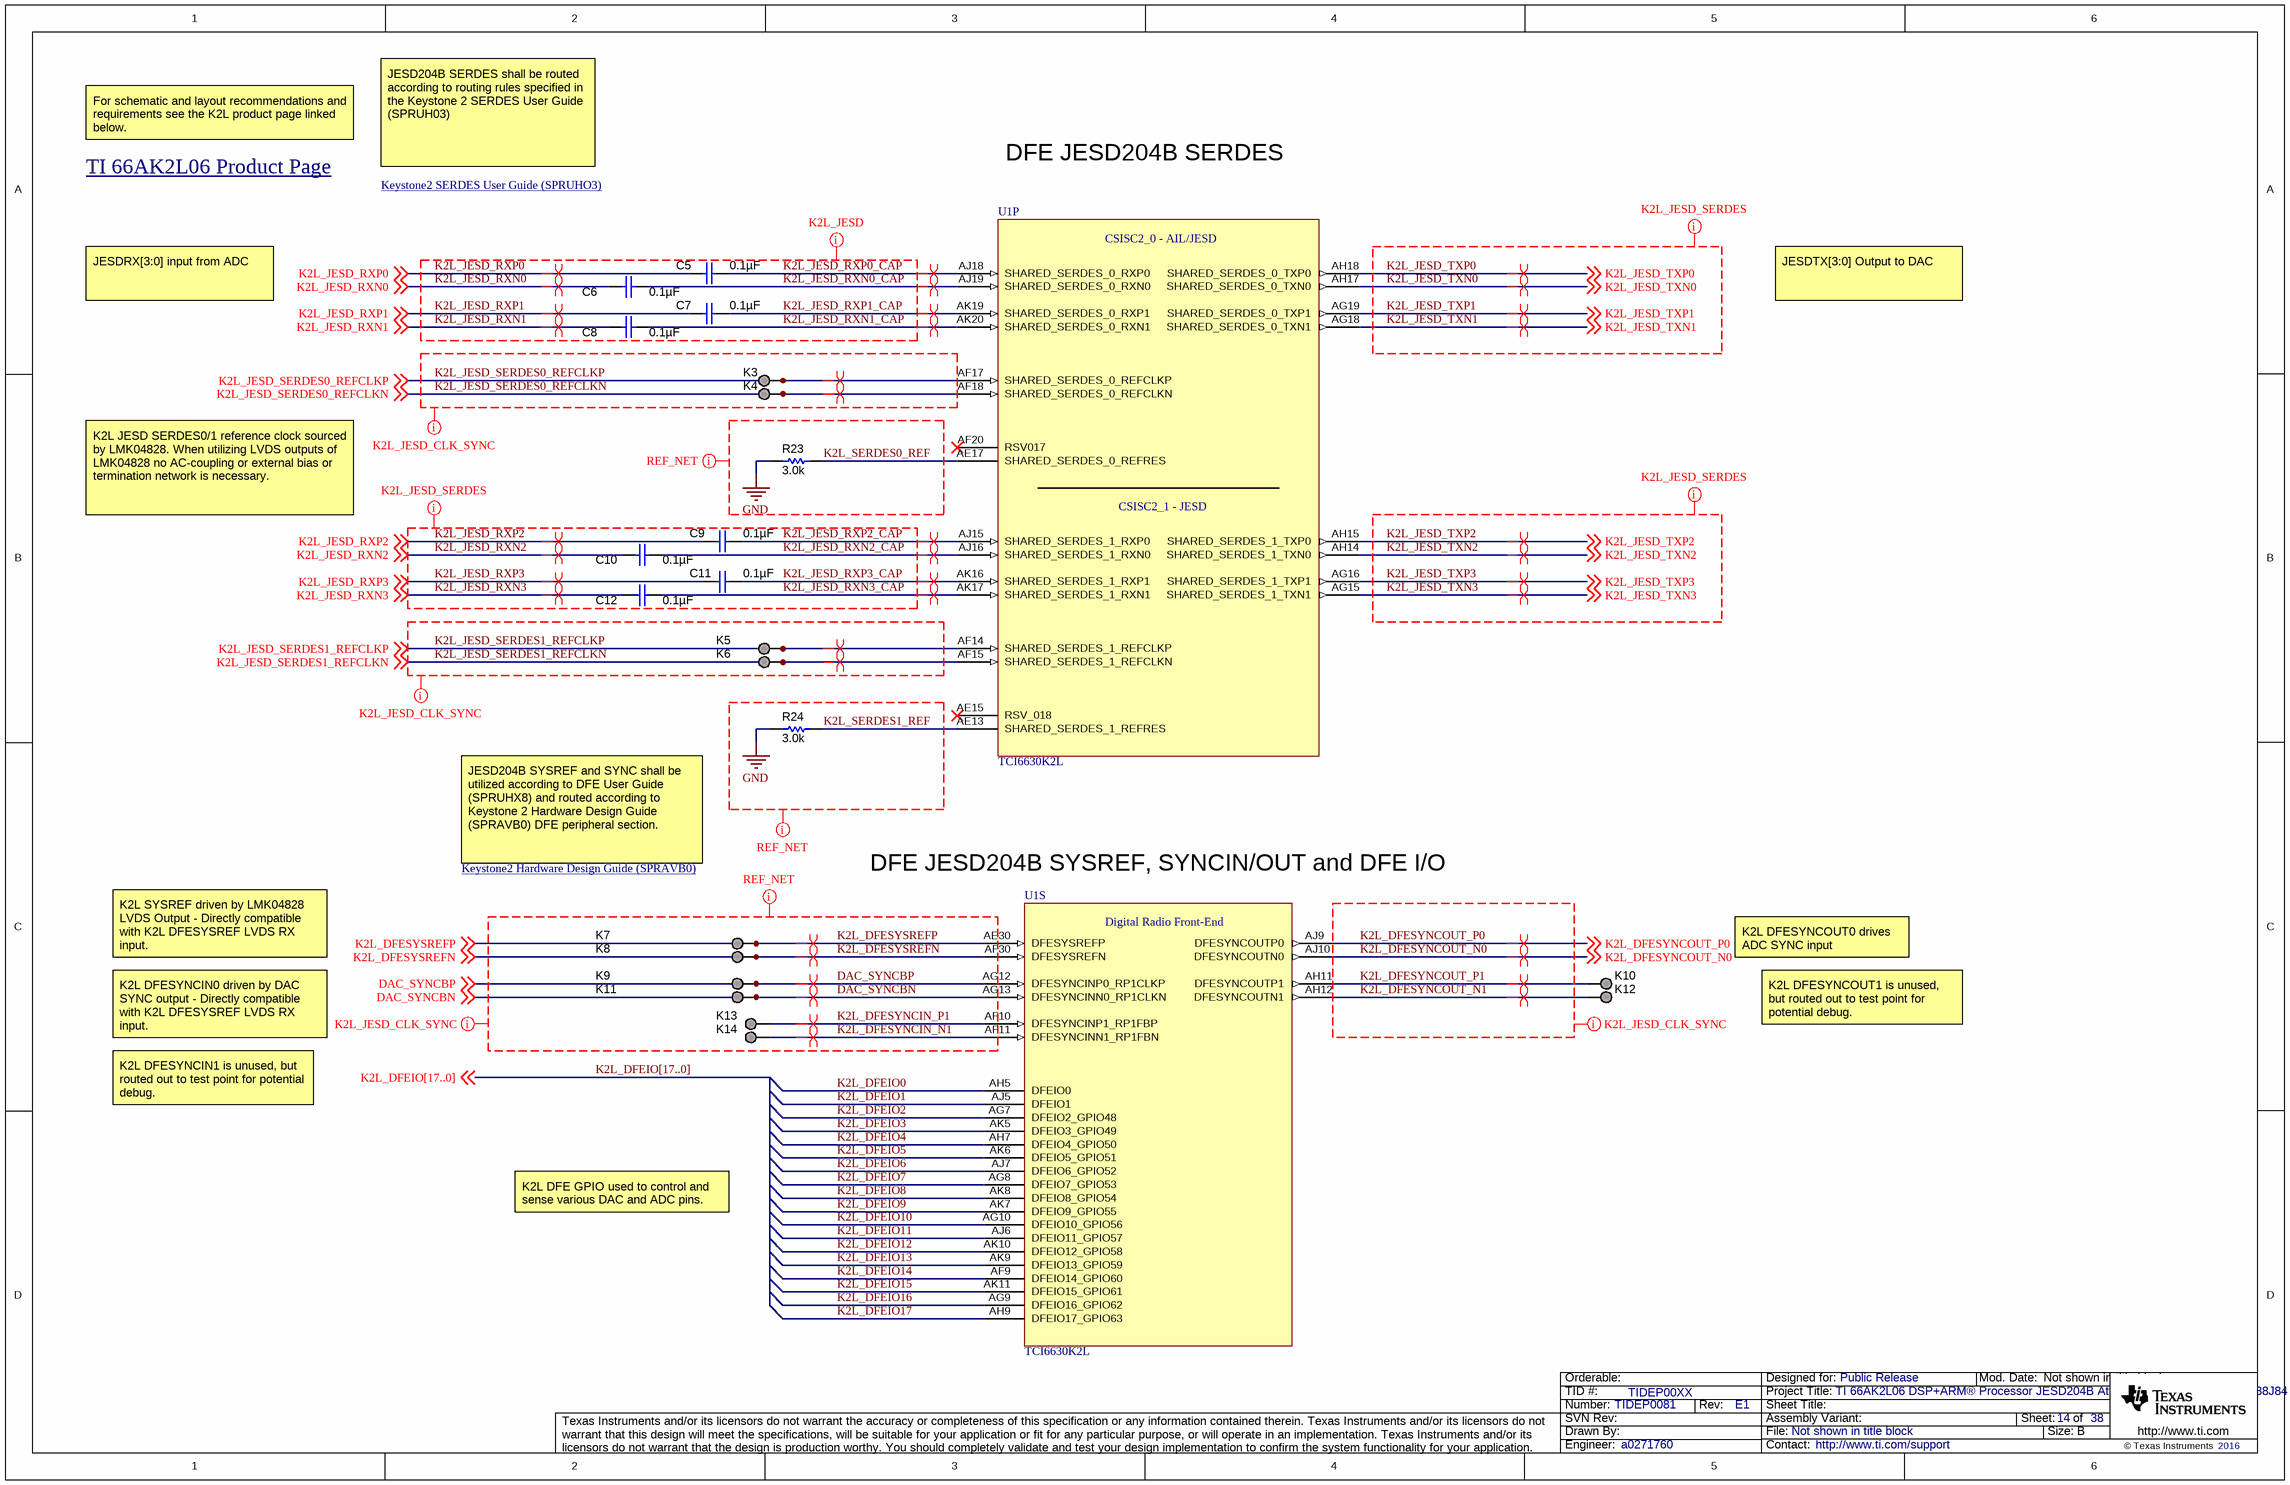
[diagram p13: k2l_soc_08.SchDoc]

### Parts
C5  ValueDisplayed: 0.1µF  [0201L]  (hidden comment: CL03A104KP3NNNC)
C6  ValueDisplayed: 0.1µF  [0201L]  (hidden comment: CL03A104KP3NNNC)
C7  ValueDisplayed: 0.1µF  [0201L]  (hidden comment: CL03A104KP3NNNC)
C8  ValueDisplayed: 0.1µF  [0201L]  (hidden comment: CL03A104KP3NNNC)
C9  ValueDisplayed: 0.1µF  [0201L]  (hidden comment: CL03A104KP3NNNC)
C10  ValueDisplayed: 0.1µF  [0201L]  (hidden comment: CL03A104KP3NNNC)
C11  ValueDisplayed: 0.1µF  [0201L]  (hidden comment: CL03A104KP3NNNC)
C12  ValueDisplayed: 0.1µF  [0201L]  (hidden comment: CL03A104KP3NNNC)
K3  TESTPOINT  [TESTPOINT]  (value not drawn)  (no BOM)
K4  TESTPOINT  [TESTPOINT]  (value not drawn)  (no BOM)
K5  TESTPOINT  [TESTPOINT]  (value not drawn)  (no BOM)
K6  TESTPOINT  [TESTPOINT]  (value not drawn)  (no BOM)
K7  TESTPOINT  [TESTPOINT]  (value not drawn)  (no BOM)
K8  TESTPOINT  [TESTPOINT]  (value not drawn)  (no BOM)
K9  TESTPOINT  [TESTPOINT]  (value not drawn)  (no BOM)
K10  TESTPOINT  [TESTPOINT]  (value not drawn)  (no BOM)
K11  TESTPOINT  [TESTPOINT]  (value not drawn)  (no BOM)
K12  TESTPOINT  [TESTPOINT]  (value not drawn)  (no BOM)
K13  TESTPOINT  [TESTPOINT]  (value not drawn)  (no BOM)
K14  TESTPOINT  [TESTPOINT]  (value not drawn)  (no BOM)
R23  ValueDisplayed: 3.0k  [0402]  (hidden comment: CRCW04023K00JNED)
R24  ValueDisplayed: 3.0k  [0402]  (hidden comment: CRCW04023K00JNED)
U1  TCI6630K2L  [BGA900C80P30X30_2500X2500X355]  (parts P,S of 24)

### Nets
GND: R23.1 R24.1  [project net DAC_OUT0N_T1]
DAC_SYNCBN: K11.1 U1.AG13(DFESYNCINN0_RP1CLKN) ; off-sheet DAC_SYNCBN
DAC_SYNCBP: K9.1 U1.AG12(DFESYNCINP0_RP1CLKP) ; off-sheet DAC_SYNCBP
K2L_DFEIO0: U1.AH5(DFEIO0)
K2L_DFEIO1: U1.AJ5(DFEIO1)
K2L_DFEIO2: U1.AG7(DFEIO2_GPIO48)
K2L_DFEIO3: U1.AK5(DFEIO3_GPIO49)
K2L_DFEIO4: U1.AH7(DFEIO4_GPIO50)
K2L_DFEIO5: U1.AK6(DFEIO5_GPIO51)
K2L_DFEIO6: U1.AJ7(DFEIO6_GPIO52)
K2L_DFEIO7: U1.AG8(DFEIO7_GPIO53)
K2L_DFEIO8: U1.AK8(DFEIO8_GPIO54)
K2L_DFEIO9: U1.AK7(DFEIO9_GPIO55)
K2L_DFEIO10: U1.AG10(DFEIO10_GPIO56)
K2L_DFEIO11: U1.AJ6(DFEIO11_GPIO57)
K2L_DFEIO12: U1.AK10(DFEIO12_GPIO58)
K2L_DFEIO13: U1.AK9(DFEIO13_GPIO59)
K2L_DFEIO14: U1.AF9(DFEIO14_GPIO60)
K2L_DFEIO15: U1.AK11(DFEIO15_GPIO61)
K2L_DFEIO16: U1.AG9(DFEIO16_GPIO62)
K2L_DFEIO17: U1.AH9(DFEIO17_GPIO63)
K2L_DFESYNCIN_N1: K14.1 U1.AF11(DFESYNCINN1_RP1FBN)
K2L_DFESYNCIN_P1: K13.1 U1.AF10(DFESYNCINP1_RP1FBP)
K2L_DFESYNCOUT_N0: U1.AJ10(DFESYNCOUTN0) ; off-sheet K2L_DFESYNCOUT_N0
K2L_DFESYNCOUT_N1: K12.1 U1.AH12(DFESYNCOUTN1)
K2L_DFESYNCOUT_P0: U1.AJ9(DFESYNCOUTP0) ; off-sheet K2L_DFESYNCOUT_P0
K2L_DFESYNCOUT_P1: K10.1 U1.AH11(DFESYNCOUTP1)
K2L_DFESYSREFN: K8.1 U1.AF30(DFESYSREFN) ; off-sheet K2L_DFESYSREFN
K2L_DFESYSREFP: K7.1 U1.AE30(DFESYSREFP) ; off-sheet K2L_DFESYSREFP
K2L_JESD_RXN0: C6.2 ; off-sheet K2L_JESD_RXN0
K2L_JESD_RXN0_CAP: C6.1 U1.AJ19(SHARED_SERDES_0_RXN0)
K2L_JESD_RXN1: C8.2 ; off-sheet K2L_JESD_RXN1
K2L_JESD_RXN1_CAP: C8.1 U1.AK20(SHARED_SERDES_0_RXN1)
K2L_JESD_RXN2: C10.2 ; off-sheet K2L_JESD_RXN2
K2L_JESD_RXN2_CAP: C10.1 U1.AJ16(SHARED_SERDES_1_RXN0)
K2L_JESD_RXN3: C12.2 ; off-sheet K2L_JESD_RXN3
K2L_JESD_RXN3_CAP: C12.1 U1.AK17(SHARED_SERDES_1_RXN1)
K2L_JESD_RXP0: C5.2 ; off-sheet K2L_JESD_RXP0
K2L_JESD_RXP0_CAP: C5.1 U1.AJ18(SHARED_SERDES_0_RXP0)
K2L_JESD_RXP1: C7.2 ; off-sheet K2L_JESD_RXP1
K2L_JESD_RXP1_CAP: C7.1 U1.AK19(SHARED_SERDES_0_RXP1)
K2L_JESD_RXP2: C9.2 ; off-sheet K2L_JESD_RXP2
K2L_JESD_RXP2_CAP: C9.1 U1.AJ15(SHARED_SERDES_1_RXP0)
K2L_JESD_RXP3: C11.2 ; off-sheet K2L_JESD_RXP3
K2L_JESD_RXP3_CAP: C11.1 U1.AK16(SHARED_SERDES_1_RXP1)
K2L_JESD_SERDES0_REFCLKN: K4.1 U1.AF18(SHARED_SERDES_0_REFCLKN) ; off-sheet K2L_JESD_SERDES0_REFCLKN
K2L_JESD_SERDES0_REFCLKP: K3.1 U1.AF17(SHARED_SERDES_0_REFCLKP) ; off-sheet K2L_JESD_SERDES0_REFCLKP
K2L_JESD_SERDES1_REFCLKN: K6.1 U1.AF15(SHARED_SERDES_1_REFCLKN) ; off-sheet K2L_JESD_SERDES1_REFCLKN
K2L_JESD_SERDES1_REFCLKP: K5.1 U1.AF14(SHARED_SERDES_1_REFCLKP) ; off-sheet K2L_JESD_SERDES1_REFCLKP
K2L_JESD_TXN0: U1.AH17(SHARED_SERDES_0_TXN0) ; off-sheet K2L_JESD_TXN0
K2L_JESD_TXN1: U1.AG18(SHARED_SERDES_0_TXN1) ; off-sheet K2L_JESD_TXN1
K2L_JESD_TXN2: U1.AH14(SHARED_SERDES_1_TXN0) ; off-sheet K2L_JESD_TXN2
K2L_JESD_TXN3: U1.AG15(SHARED_SERDES_1_TXN1) ; off-sheet K2L_JESD_TXN3
K2L_JESD_TXP0: U1.AH18(SHARED_SERDES_0_TXP0) ; off-sheet K2L_JESD_TXP0
K2L_JESD_TXP1: U1.AG19(SHARED_SERDES_0_TXP1) ; off-sheet K2L_JESD_TXP1
K2L_JESD_TXP2: U1.AH15(SHARED_SERDES_1_TXP0) ; off-sheet K2L_JESD_TXP2
K2L_JESD_TXP3: U1.AG16(SHARED_SERDES_1_TXP1) ; off-sheet K2L_JESD_TXP3
K2L_SERDES0_REF: R23.2 U1.AE17(SHARED_SERDES_0_REFRES)
K2L_SERDES1_REF: R24.2 U1.AE13(SHARED_SERDES_1_REFRES)

Not connected (* = marked no-connect by the designer): U1 AE15(RSV_018)* AF20(RSV017)*

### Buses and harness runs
bus K2L_DFEIO[17..0]

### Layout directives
differential pair: DAC_SYNCBN, DAC_SYNCBP, K2L_DFESYNCIN_N1, K2L_DFESYNCIN_P1, K2L_DFESYNCOUT_N0, K2L_DFESYNCOUT_N1, K2L_DFESYNCOUT_P0, K2L_DFESYNCOUT_P1, K2L_DFESYSREFN, K2L_DFESYSREFP, K2L_JESD_RXN0, K2L_JESD_RXN0_CAP, K2L_JESD_RXN1, K2L_JESD_RXN1_CAP, K2L_JESD_RXN2, K2L_JESD_RXN2_CAP, K2L_JESD_RXN3, K2L_JESD_RXN3_CAP, K2L_JESD_RXP0, K2L_JESD_RXP0_CAP, K2L_JESD_RXP1, K2L_JESD_RXP1_CAP, K2L_JESD_RXP2, K2L_JESD_RXP2_CAP, K2L_JESD_RXP3, K2L_JESD_RXP3_CAP, K2L_JESD_SERDES0_REFCLKN, K2L_JESD_SERDES0_REFCLKP, K2L_JESD_SERDES1_REFCLKN, K2L_JESD_SERDES1_REFCLKP, K2L_JESD_TXN0, K2L_JESD_TXN1, K2L_JESD_TXN2, K2L_JESD_TXN3, K2L_JESD_TXP0, K2L_JESD_TXP1, K2L_JESD_TXP2, K2L_JESD_TXP3
net class Undefined: DAC_SYNCBN, DAC_SYNCBP, GND, K2L_DFESYNCIN_N1, K2L_DFESYNCIN_P1, K2L_DFESYNCOUT_N0, K2L_DFESYNCOUT_N1, K2L_DFESYNCOUT_P0, K2L_DFESYNCOUT_P1, K2L_DFESYSREFN, K2L_DFESYSREFP, K2L_JESD_RXN0, K2L_JESD_RXN0_CAP, K2L_JESD_RXN1, K2L_JESD_RXN1_CAP, K2L_JESD_RXN2, K2L_JESD_RXN2_CAP, K2L_JESD_RXN3, K2L_JESD_RXN3_CAP, K2L_JESD_RXP0, K2L_JESD_RXP0_CAP, K2L_JESD_RXP1, K2L_JESD_RXP1_CAP, K2L_JESD_RXP2, K2L_JESD_RXP2_CAP, K2L_JESD_RXP3, K2L_JESD_RXP3_CAP, K2L_JESD_SERDES0_REFCLKN, K2L_JESD_SERDES0_REFCLKP, K2L_JESD_SERDES1_REFCLKN, K2L_JESD_SERDES1_REFCLKP, K2L_JESD_TXN0, K2L_JESD_TXN1, K2L_JESD_TXN2, K2L_JESD_TXN3, K2L_JESD_TXP0, K2L_JESD_TXP1, K2L_JESD_TXP2, K2L_JESD_TXP3, K2L_SERDES0_REF, K2L_SERDES1_REF

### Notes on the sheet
- For schematic and layout recommendations and requirements see the K2L product page linked below.
- JESD204B SERDES shall be routed according to routing rules specified in the Keystone 2 SERDES User Guide (SPRUH03)
- DFE JESD204B SERDES
- TI 66AK2L06 Product Page <http://www.ti.com/lsds/ti/dsp/keystone_arm/66ak2lx/overview.page>
- Keystone2 SERDES User Guide (SPRUHO3) <http://www.ti.com/lit/ug/spruho3/spruho3.pdf>
- JESDRX[3:0] input from ADC
- JESDTX[3:0] Output to DAC
- K2L JESD SERDES0/1 reference clock sourced by LMK04828. When utilizing LVDS outputs of LMK04828 no AC-coupling or external bias or termination network is necessary.
- JESD204B SYSREF and SYNC shall be utilized according to DFE User Guide (SPRUHX8) and routed according to Keystone 2 Hardware Design Guide (SPRAVB0) DFE peripheral section.
- Keystone2 Hardware Design Guide (SPRAVB0) <http://www.ti.com/lit/an/sprabv0/sprabv0.pdf>
- DFE JESD204B SYSREF, SYNCIN/OUT and DFE I/O
- K2L SYSREF driven by LMK04828 LVDS Output - Directly compatible with K2L DFESYSREF LVDS RX input.
- K2L DFESYNCOUT0 drives ADC SYNC input
- K2L DFESYNCIN0 driven by DAC SYNC output - Directly compatible with K2L DFESYSREF LVDS RX input.
- K2L DFESYNCOUT1 is unused, but routed out to test point for potential debug.
- K2L DFESYNCIN1 is unused, but routed out to test point for potential debug.
- K2L DFE GPIO used to control and sense various DAC and ADC pins.

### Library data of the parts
C5-C12 = CL03A104KP3NNNC: CAP, CERM, 0.1 µF, 10 V, +/- 10%, X5R, 0201; Manufacturer: Samsung; Polarized: N; CompType: Capacitor; Value: 0.1uF; U/M: EA; Cap_F: 0.0000001; Tolerance_%: 10; Value1: Unknown; Value2: 10V; TaMin_C: -55; TaMax_C: 85; Cap_Case: 0201
K3-K14 = TESTPOINT: TEST POINT.  No entry in BOM.
R23 R24 = CRCW04023K00JNED: RES, 3.0 k, 5%, 0.063 W, 0402; Manufacturer: Vishay-Dale; CompType: Resistor; Value: 3.0k; Res_ohm: 3000; Value_Code: 3k00; Tolerance_%: 5; Power_W: 0.063; Value2: 0.063W; VDC_V: 50; TempCo: 200 ppm/C; EIA_Code: E24; U/M: EA
U1 = lamarr_soc_TCI6630K2L: as U1 on sheet k2l_soc_03_1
